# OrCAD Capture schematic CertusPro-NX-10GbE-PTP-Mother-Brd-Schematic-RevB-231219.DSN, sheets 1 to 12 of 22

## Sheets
1 22_PS-FMC_3V3LDO: size A3; title: 22_PS-FMC_3V3_LDO; rev: v2.1
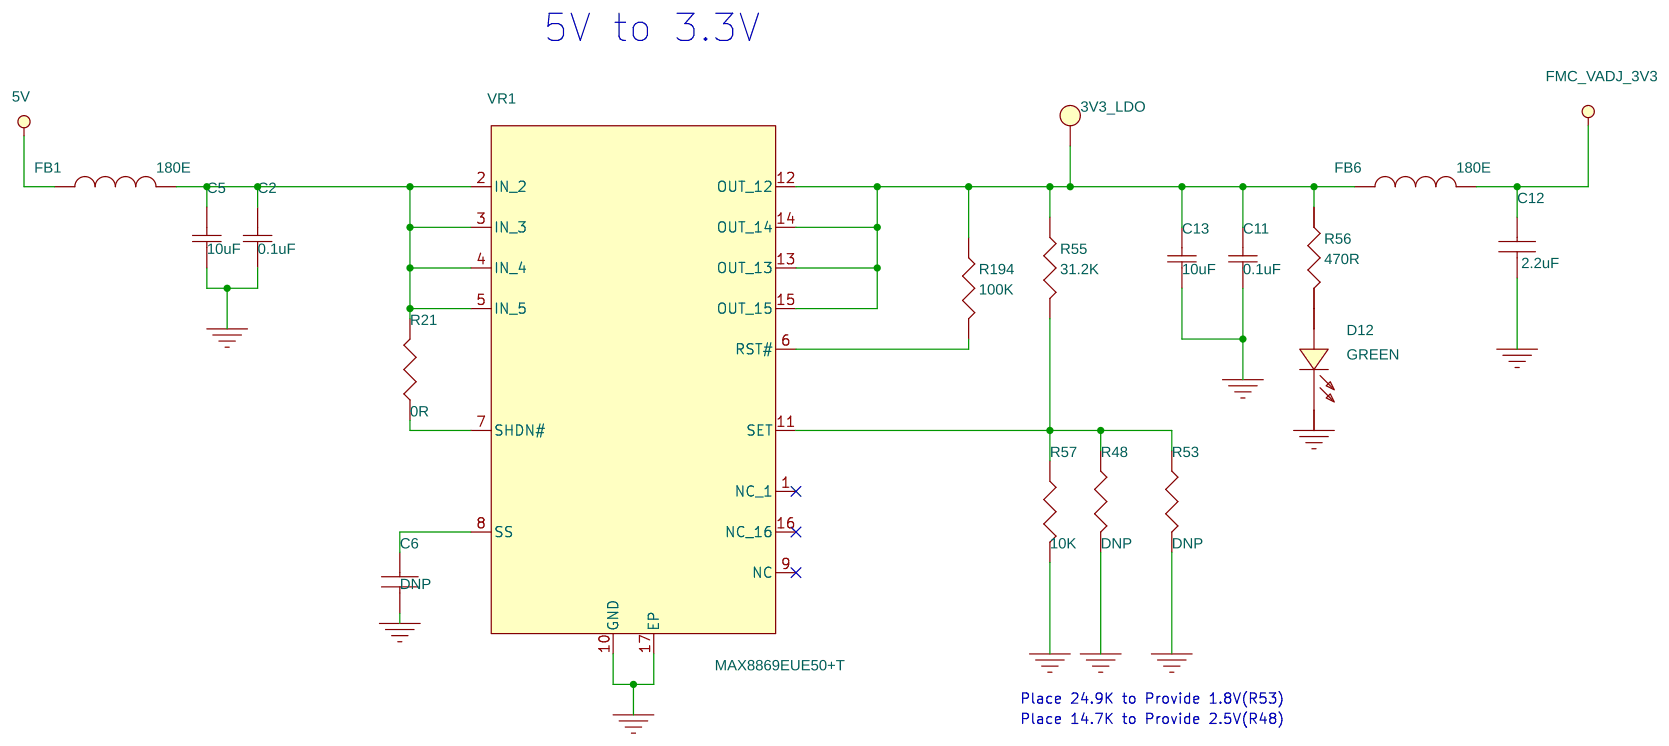
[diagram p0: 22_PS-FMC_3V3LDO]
2 18_FMC_Connector_2: size A3; title: 18_FMC_Connector
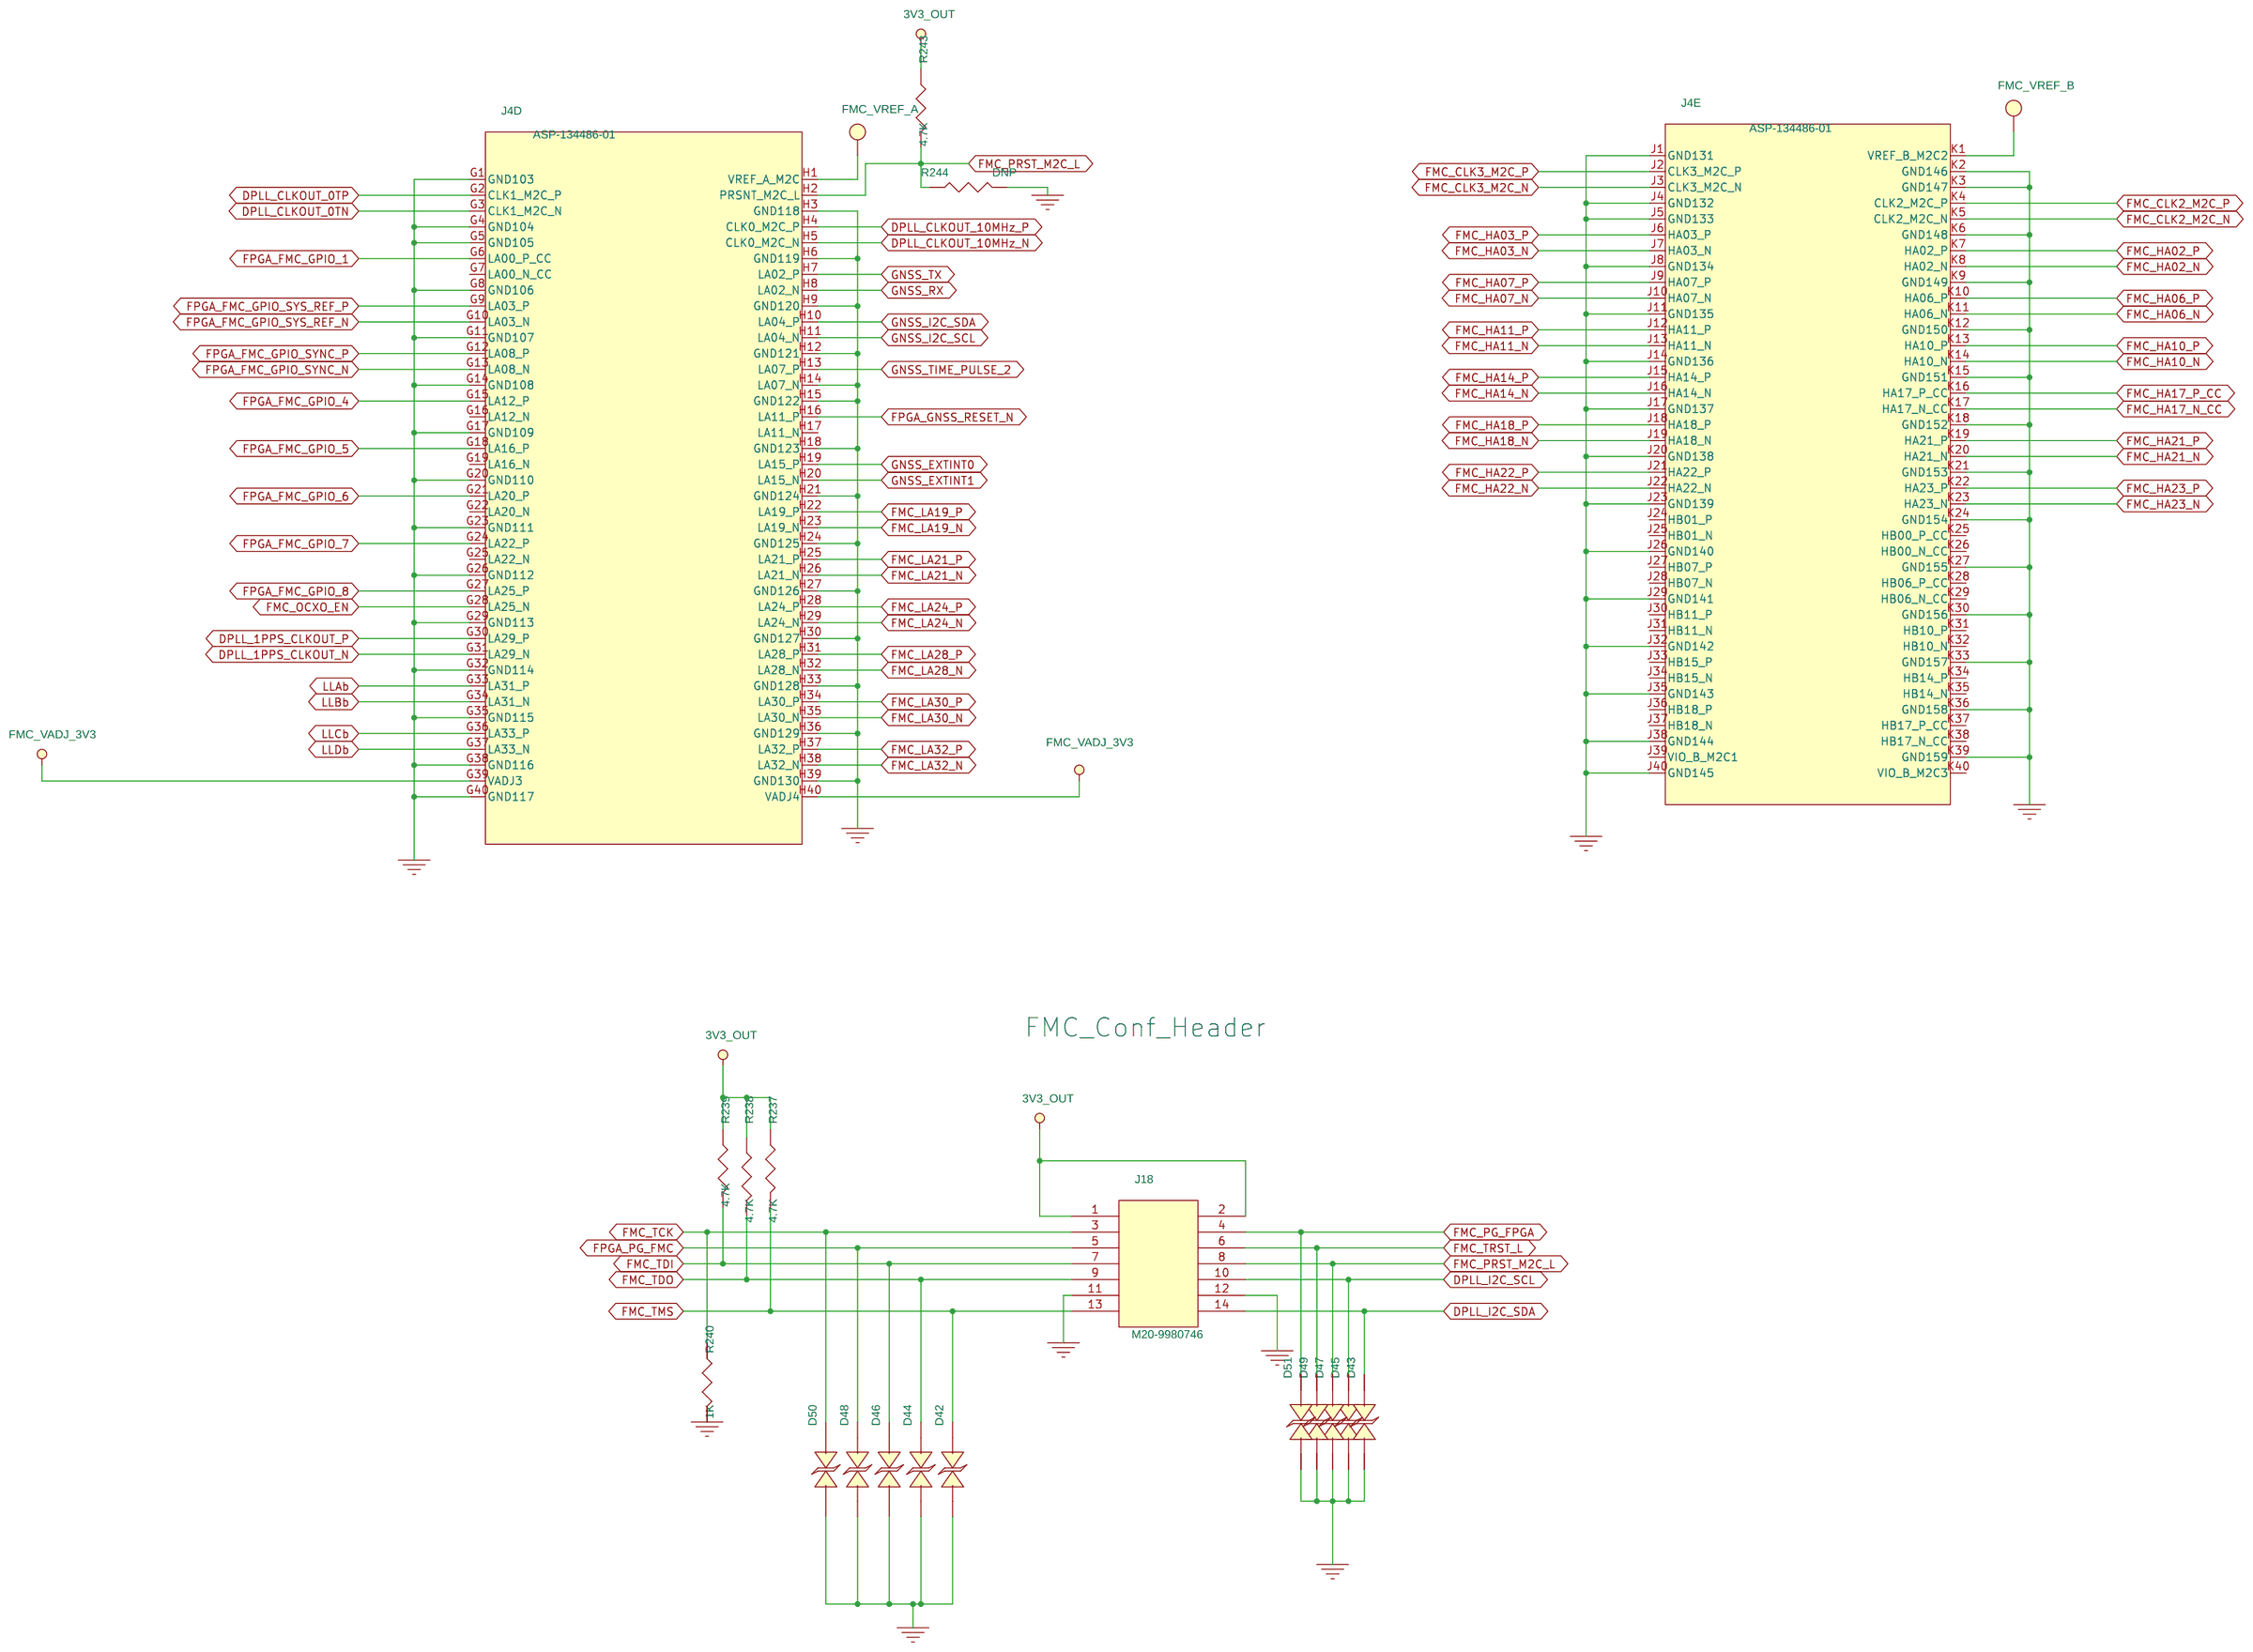
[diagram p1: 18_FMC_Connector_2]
3 04_Clock_Tree: title: 04_Clock_Tree
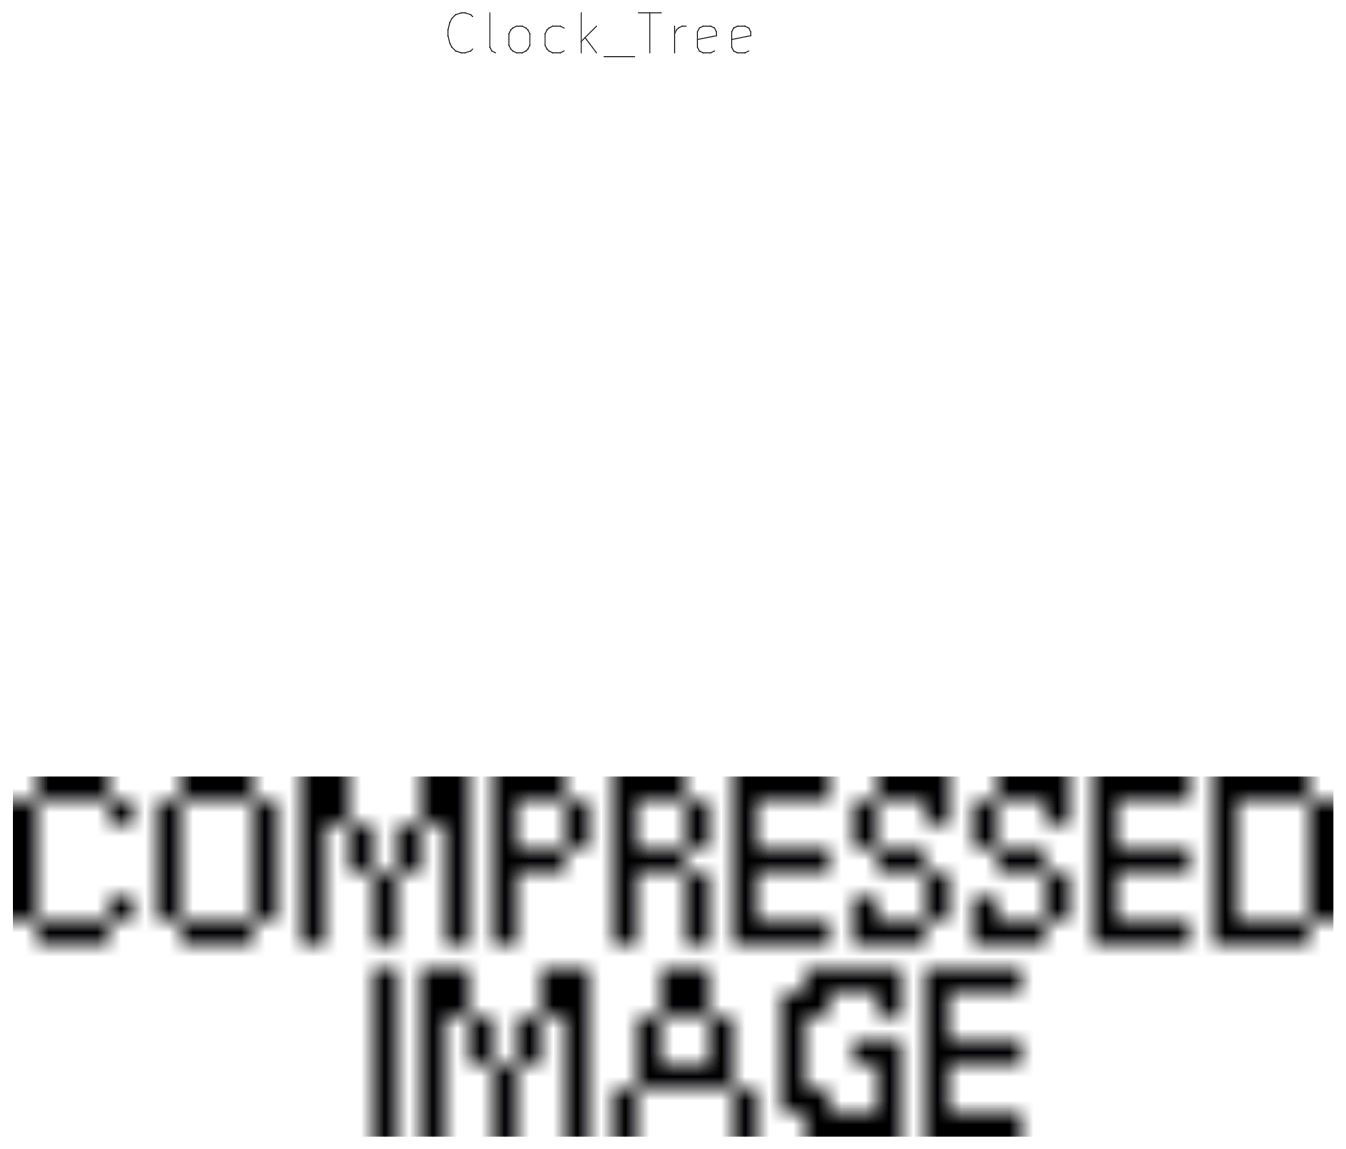
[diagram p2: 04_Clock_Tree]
4 05_PWR_Tree: title: 05_PWR_Tree
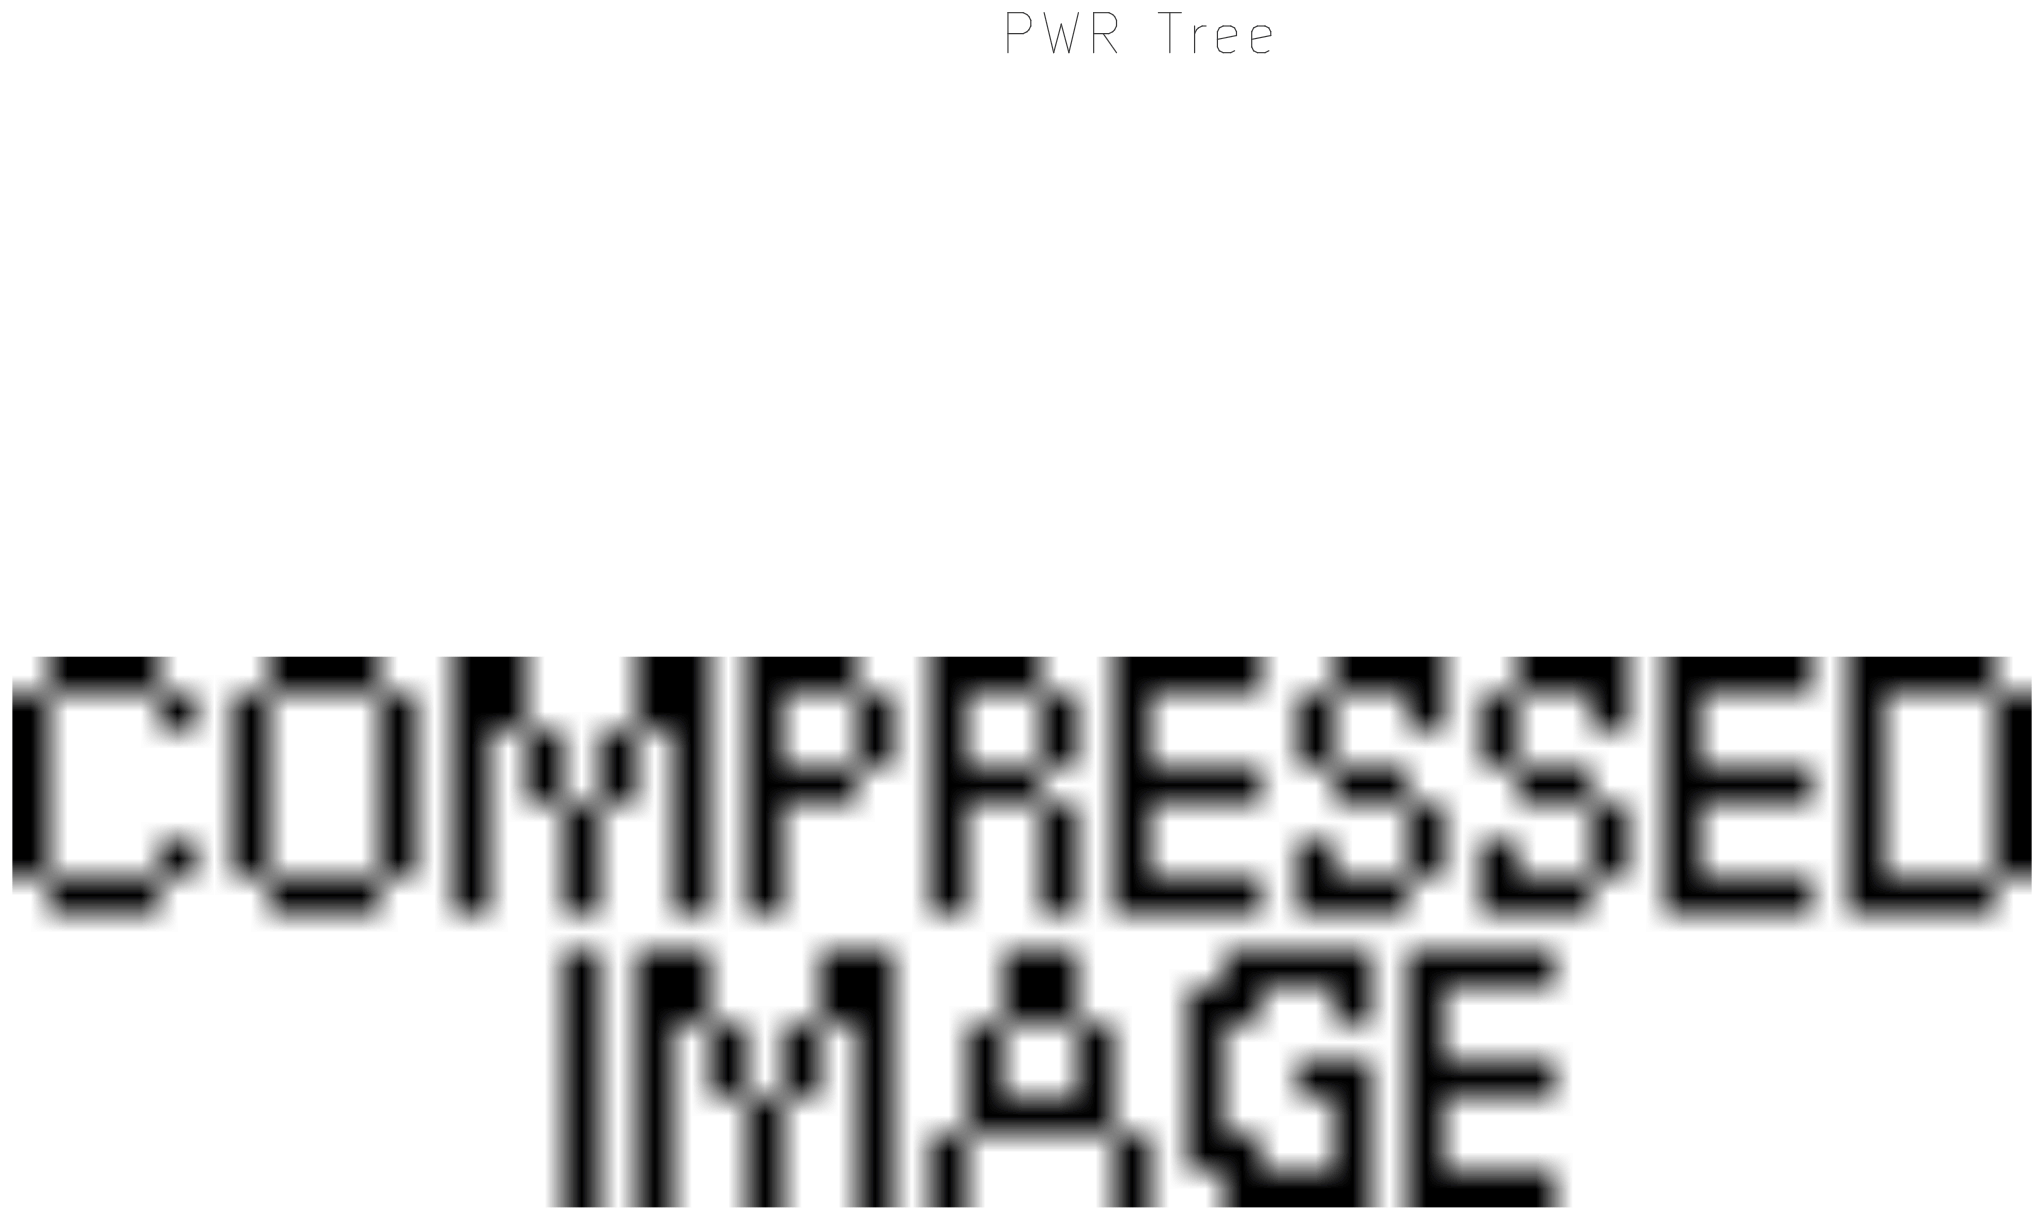
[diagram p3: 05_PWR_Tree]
5 02_Revion_Record: title: 02_Title_Block
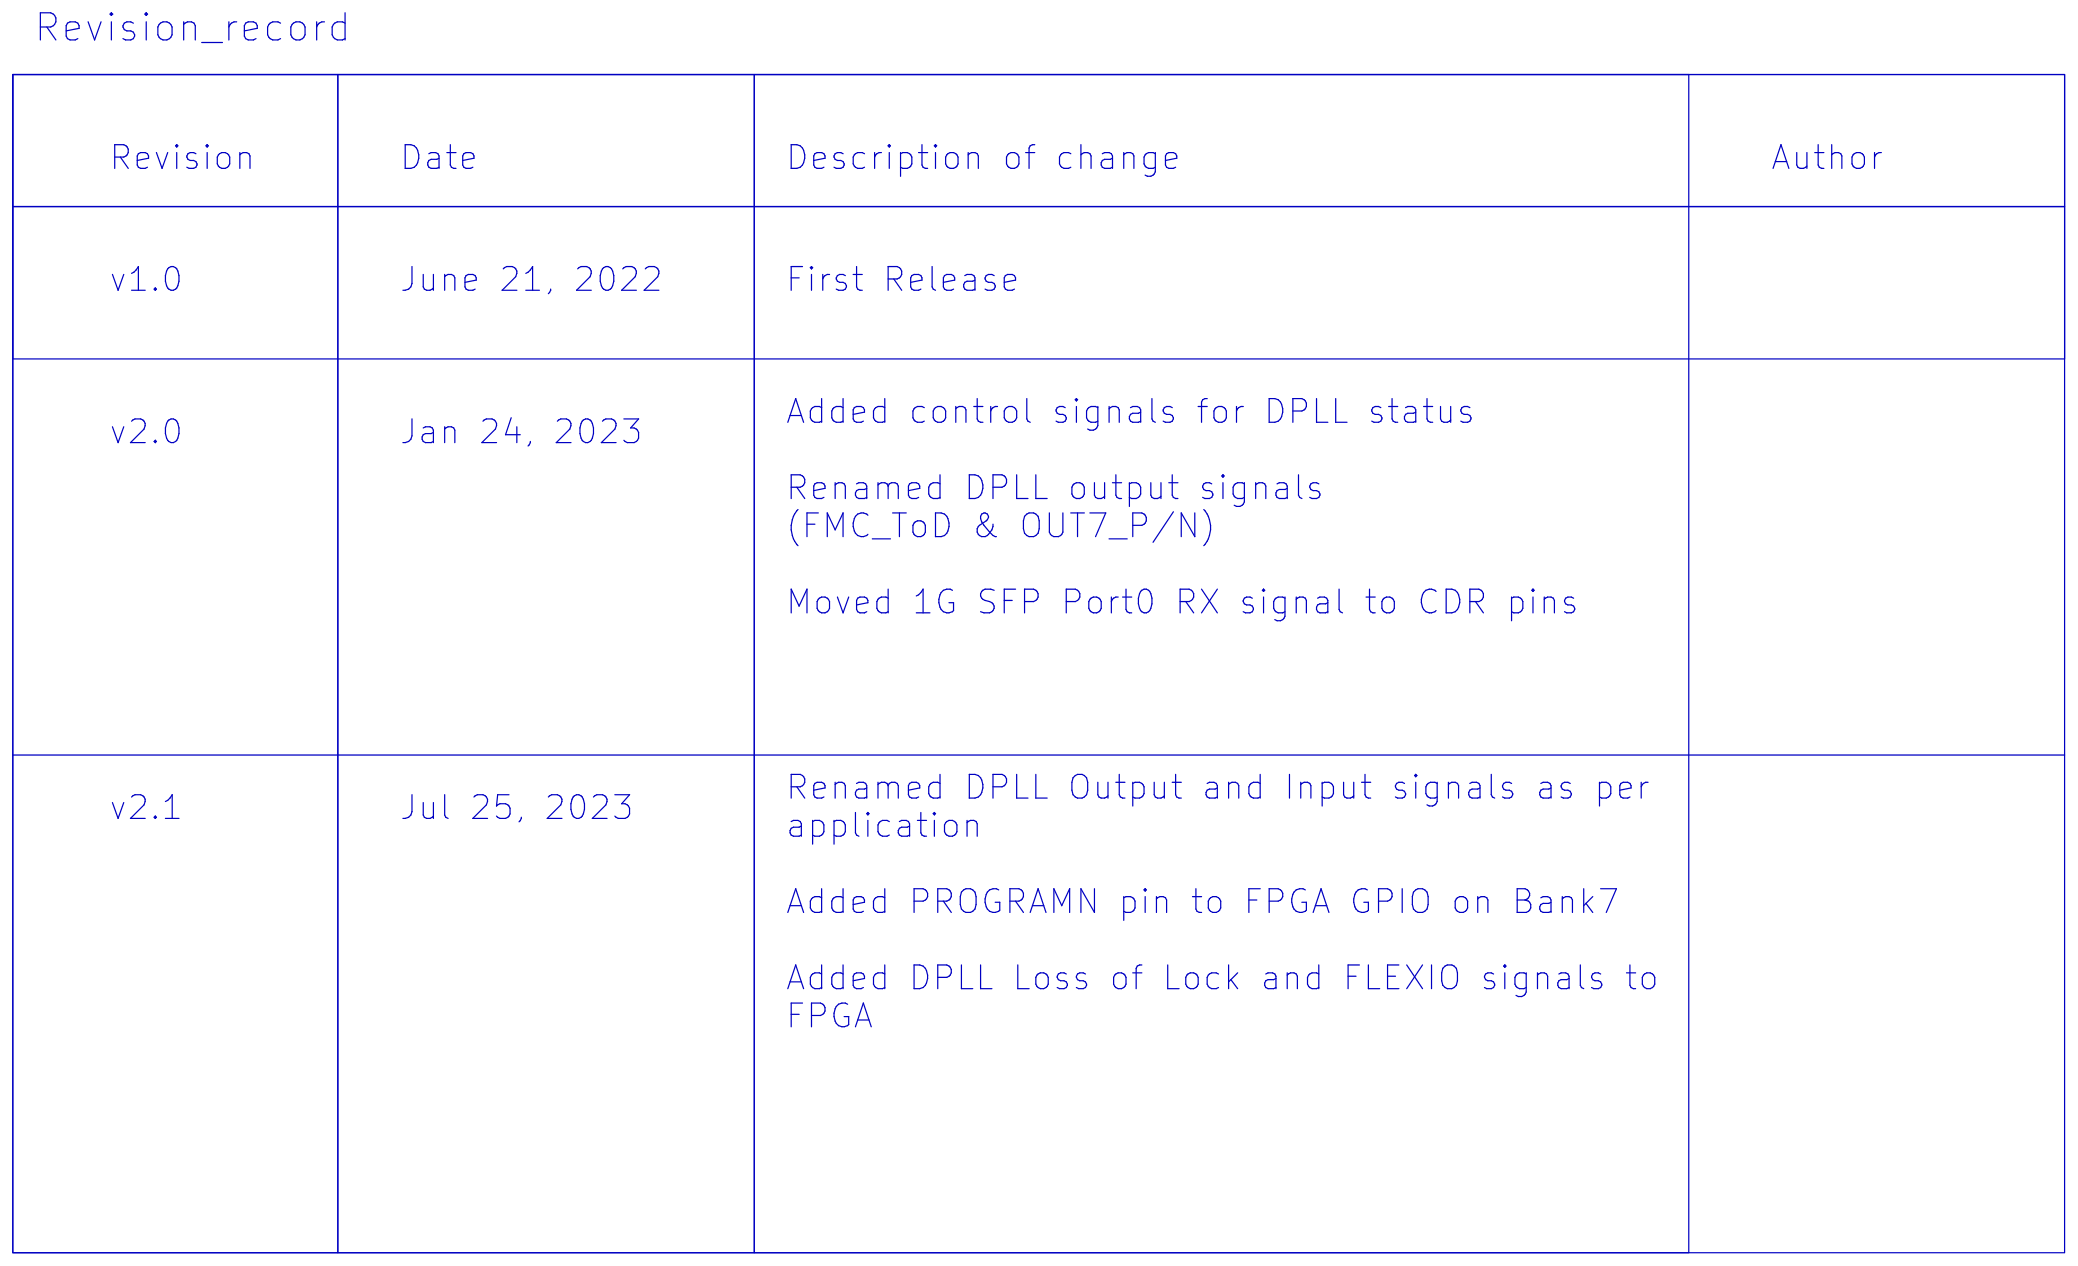
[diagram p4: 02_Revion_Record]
6 13_FPGA_B6-SFPS_Ctrl: size A3; title: 13_FPGA_B6-SFPS_Ctrl
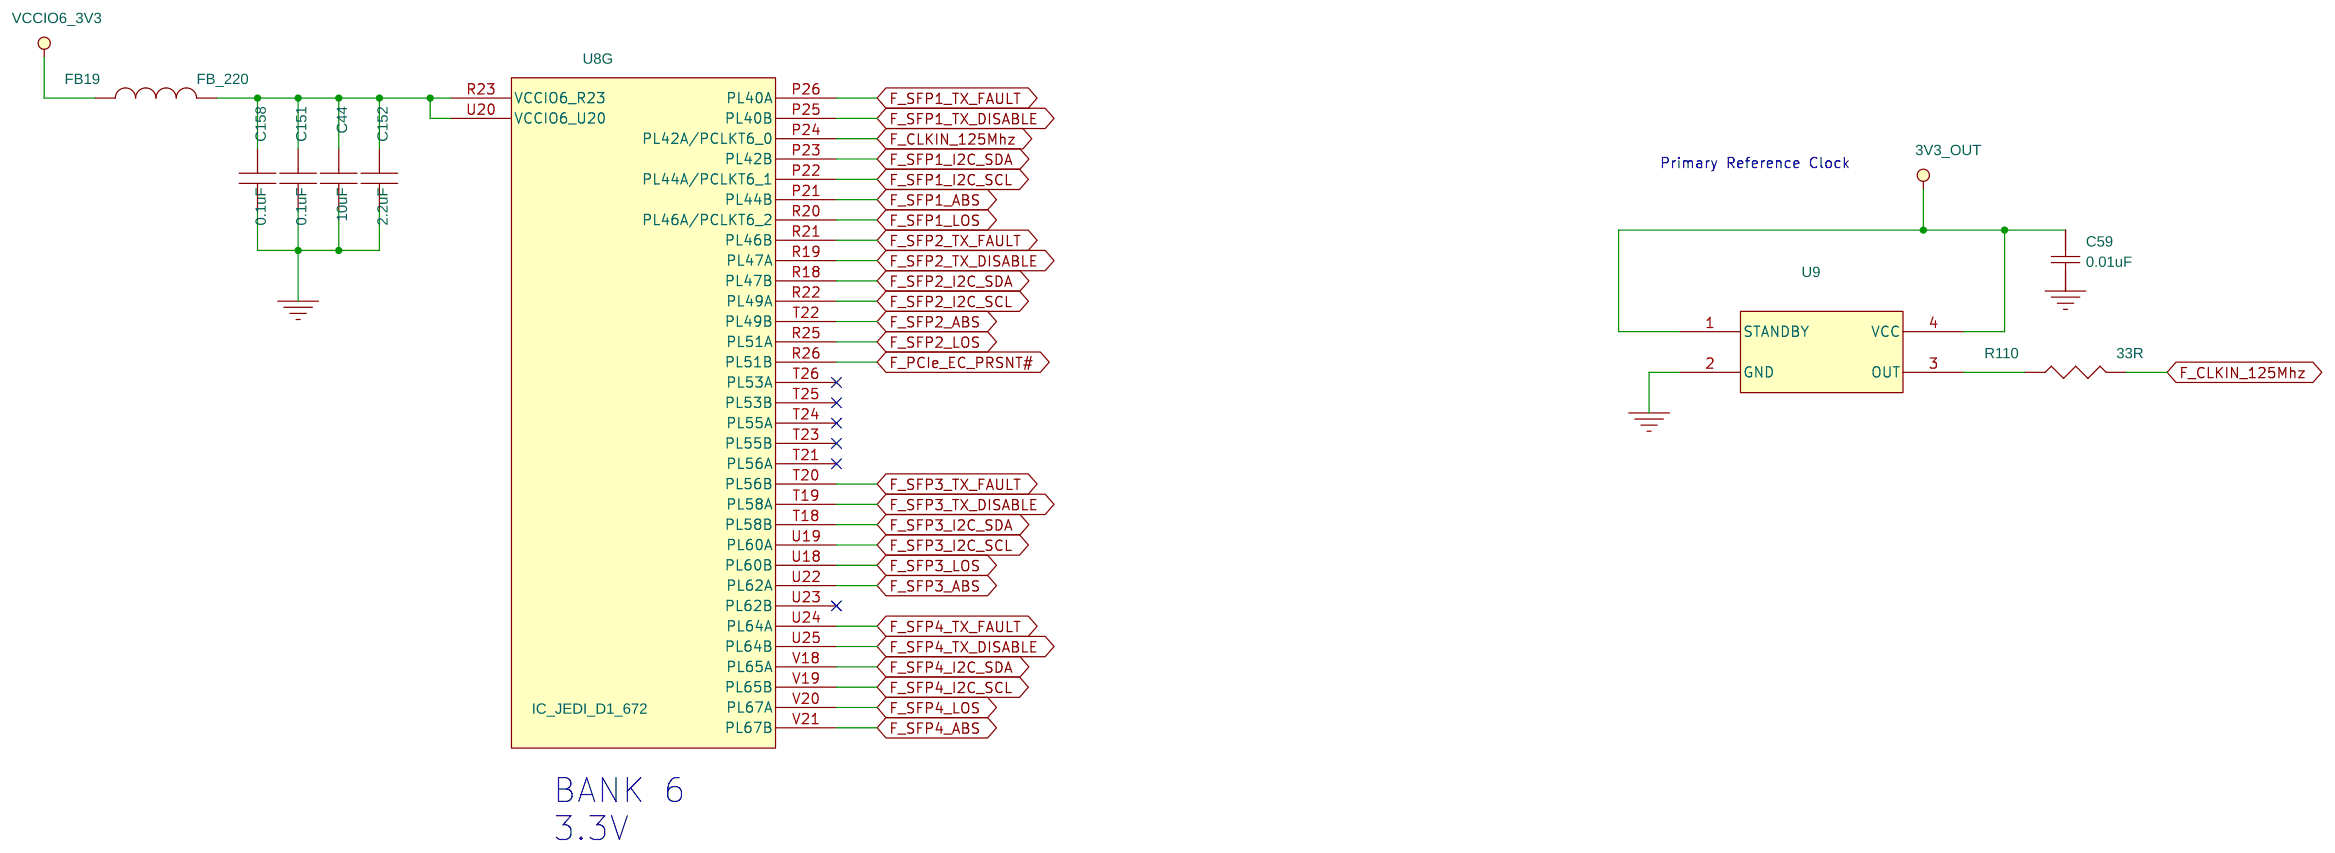
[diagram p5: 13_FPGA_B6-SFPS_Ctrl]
7 17_FMC_Connector_1: size A3; title: 17_FMC_Connector
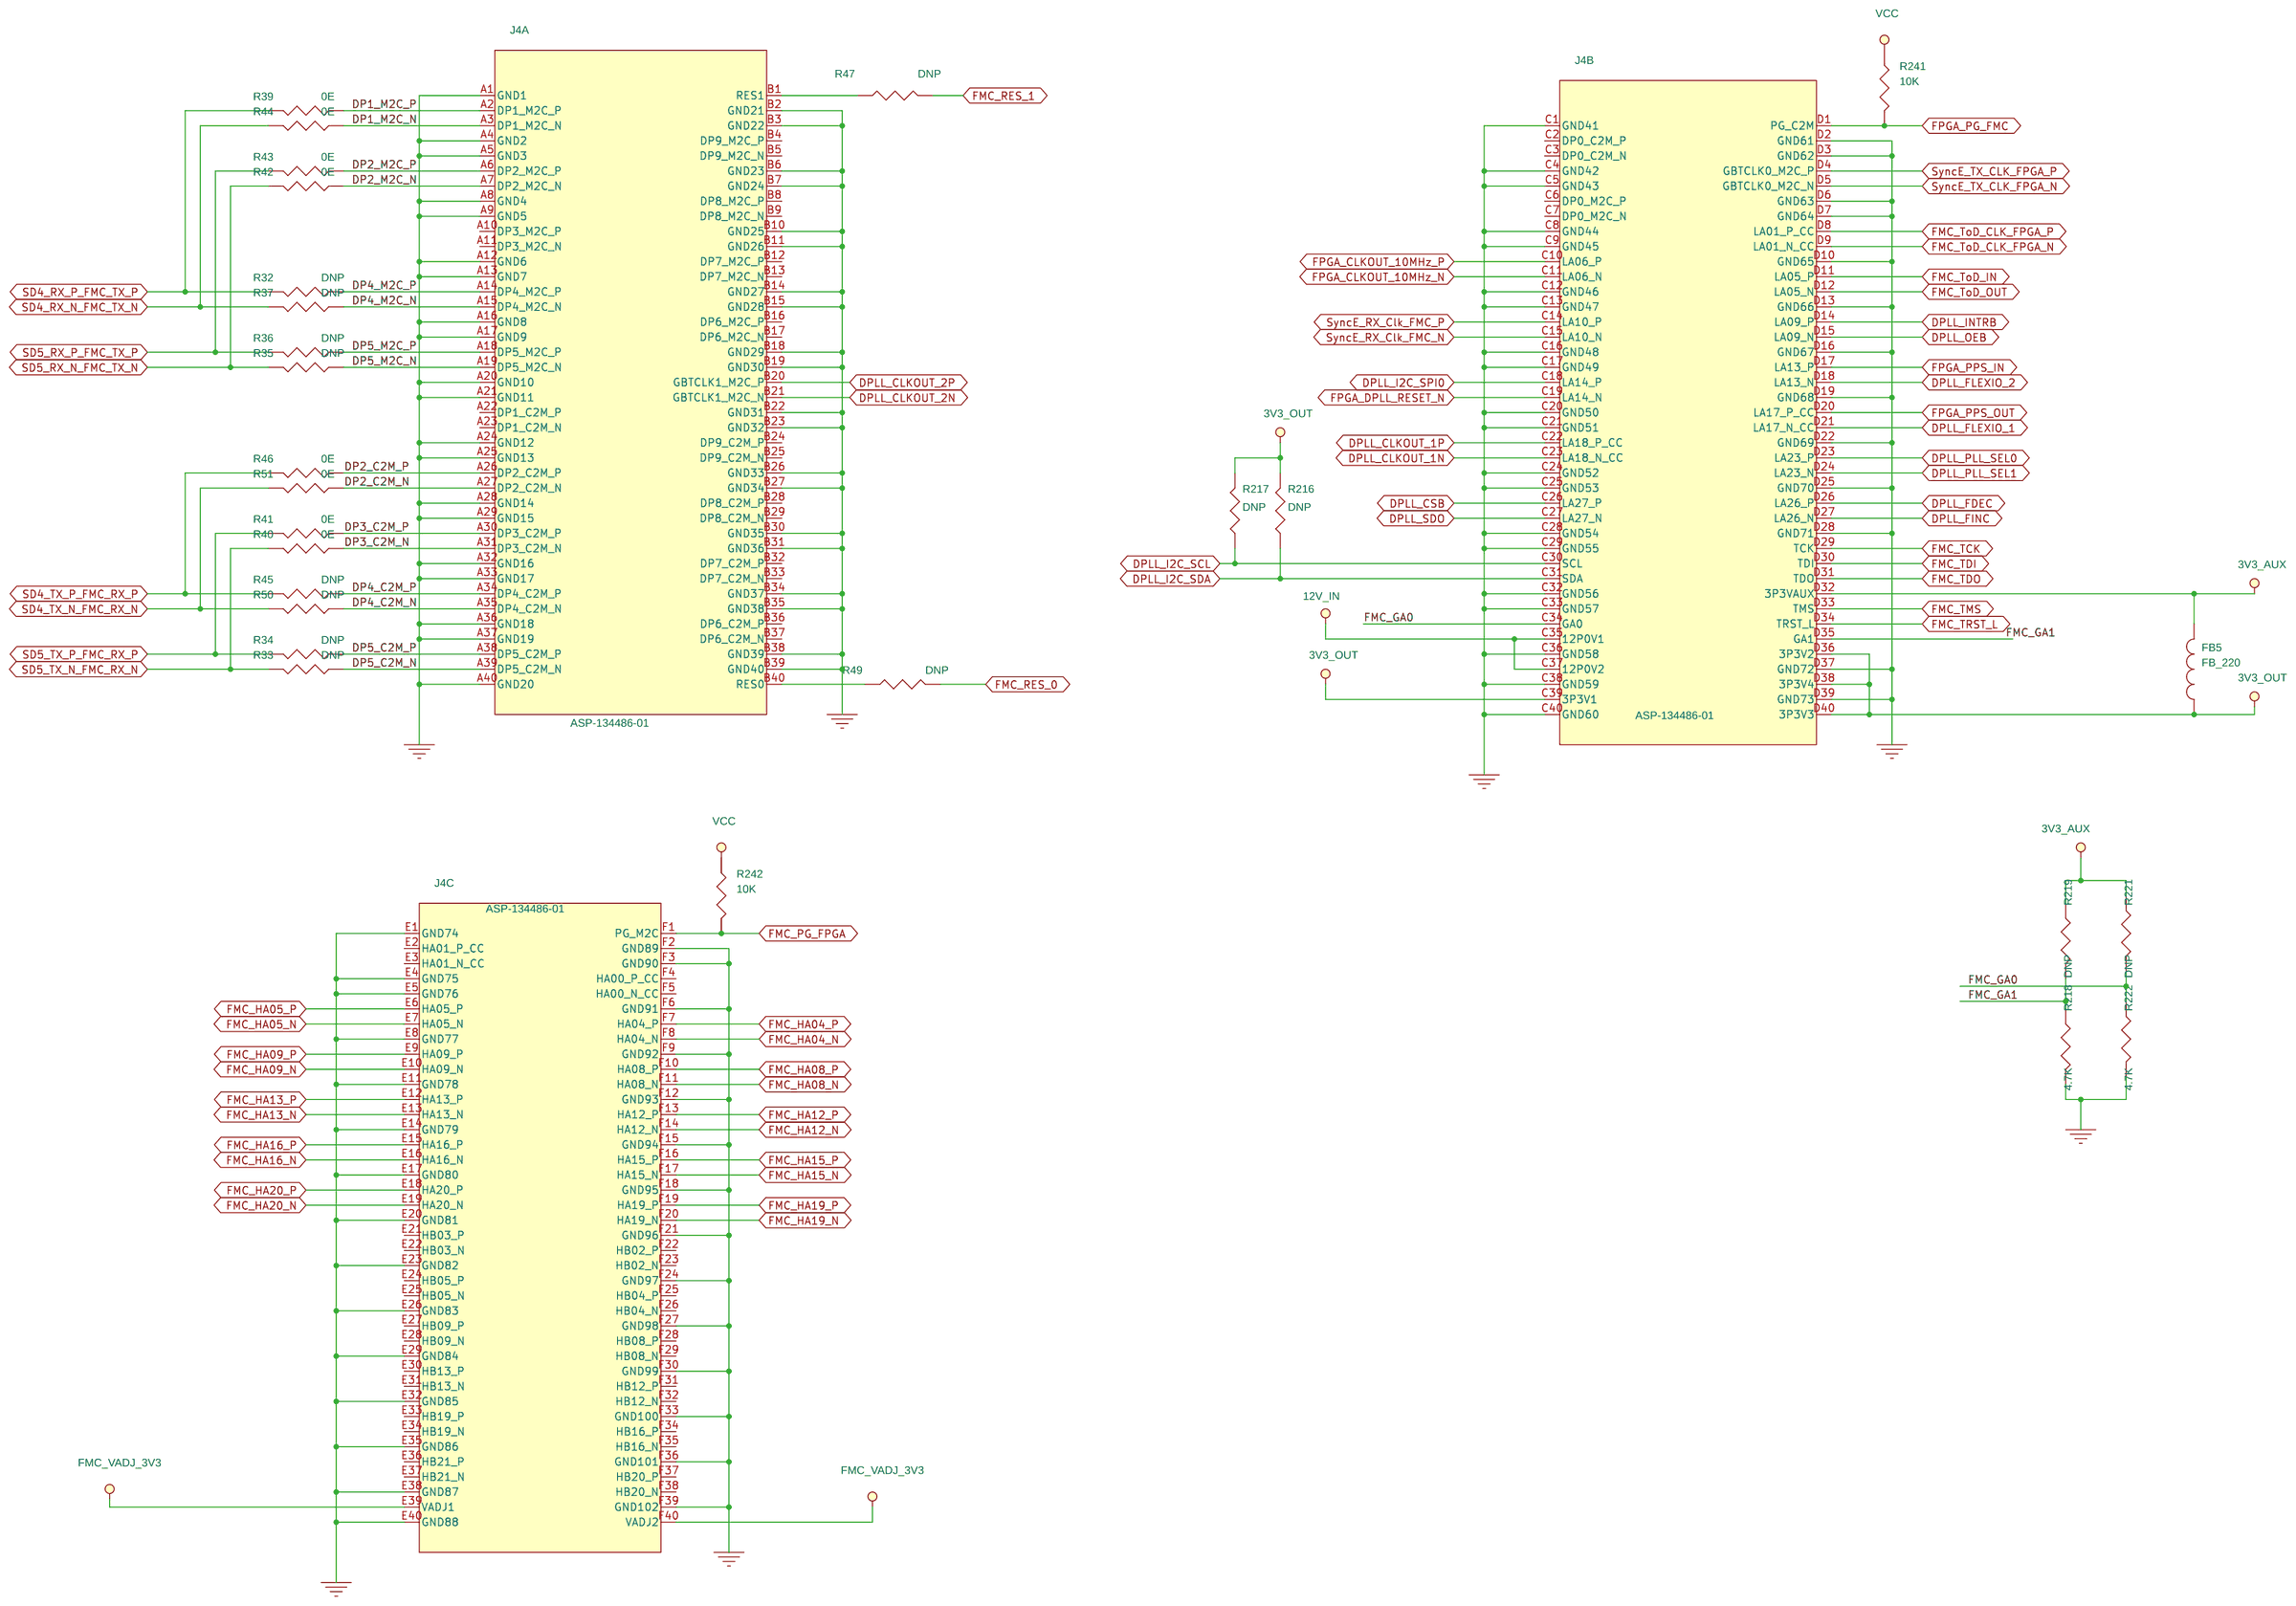
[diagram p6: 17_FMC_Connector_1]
8 21_PS-3V3,1V8LDO,2V5LDO: size A3; title: 21_PS-3V3,1V8LDO,2V5LDO
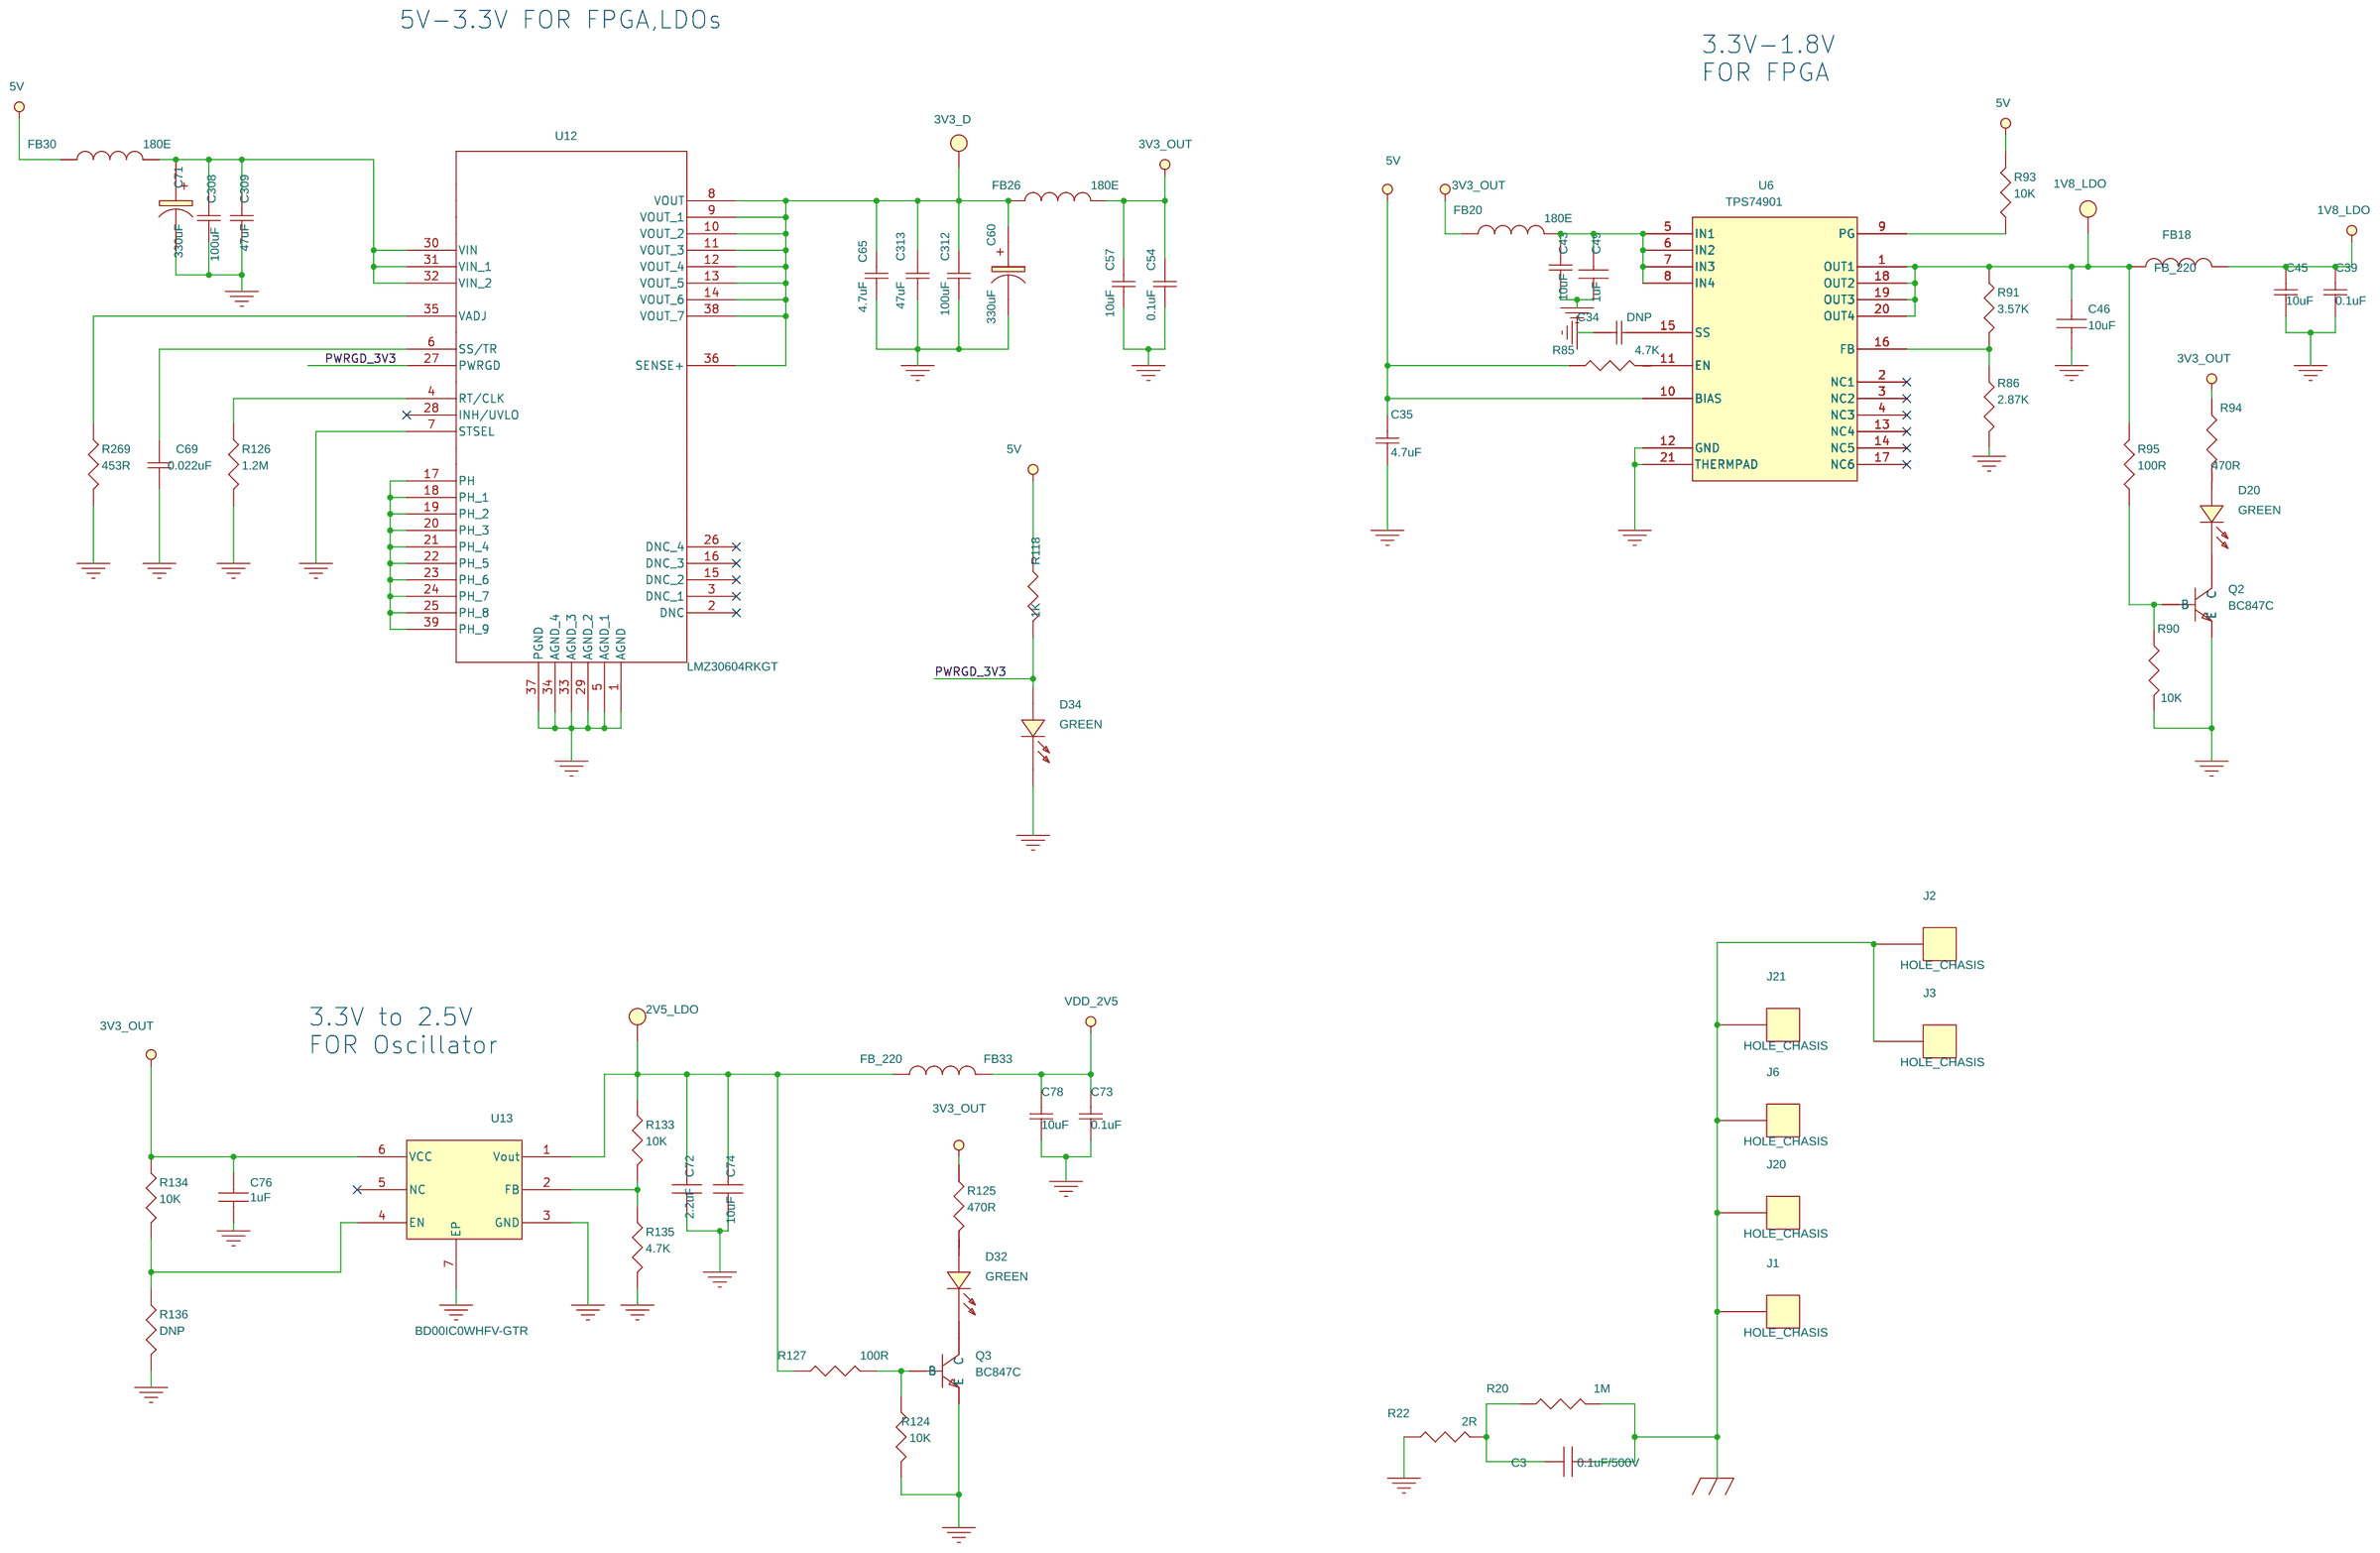
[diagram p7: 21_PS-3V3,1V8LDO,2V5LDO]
9 11_FPGA_B3_B4-FMC: size A3; title: 11_FPGA_B3_B4-FMC
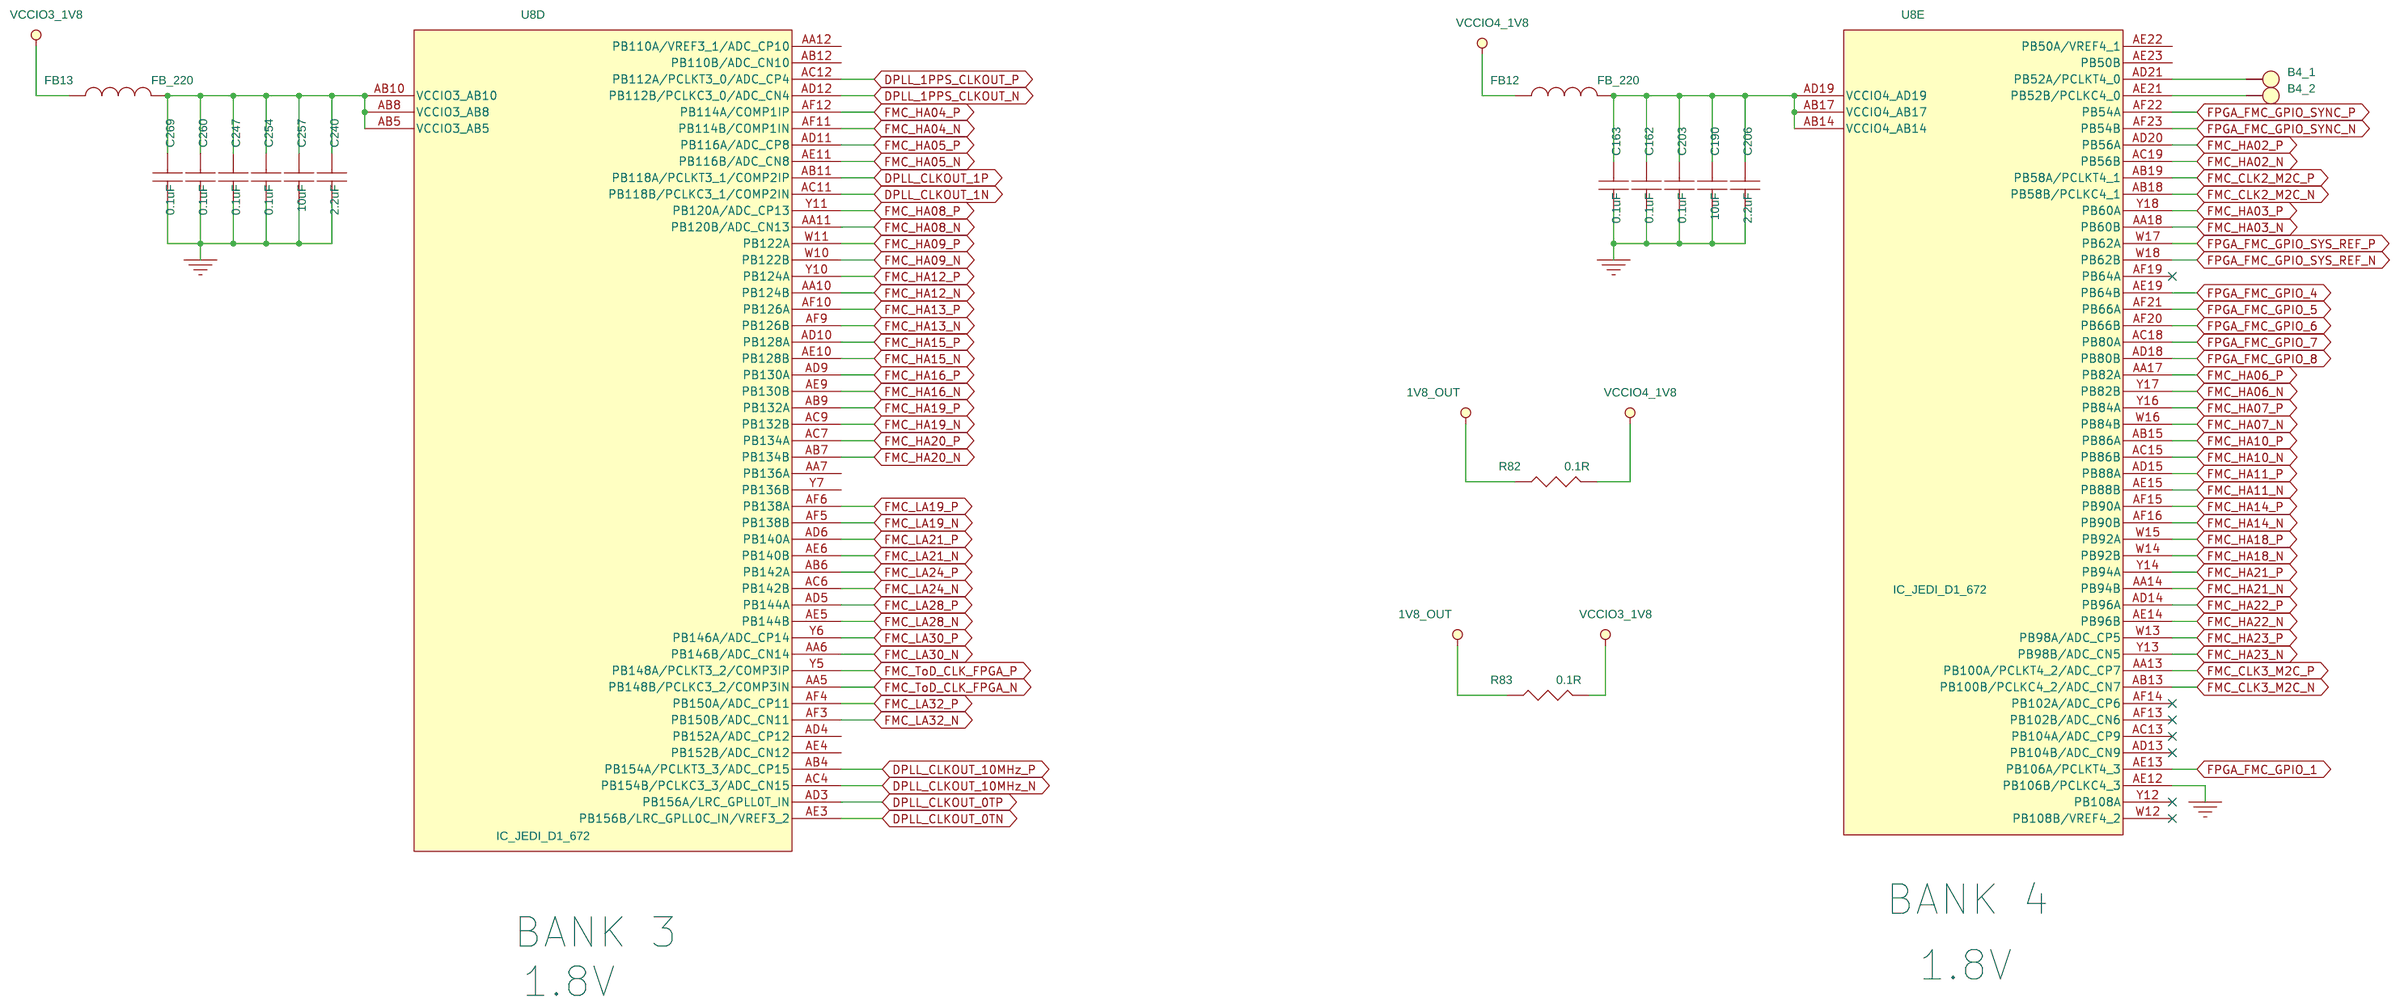
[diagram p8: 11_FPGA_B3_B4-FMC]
10 01_Index: title: 01_Index
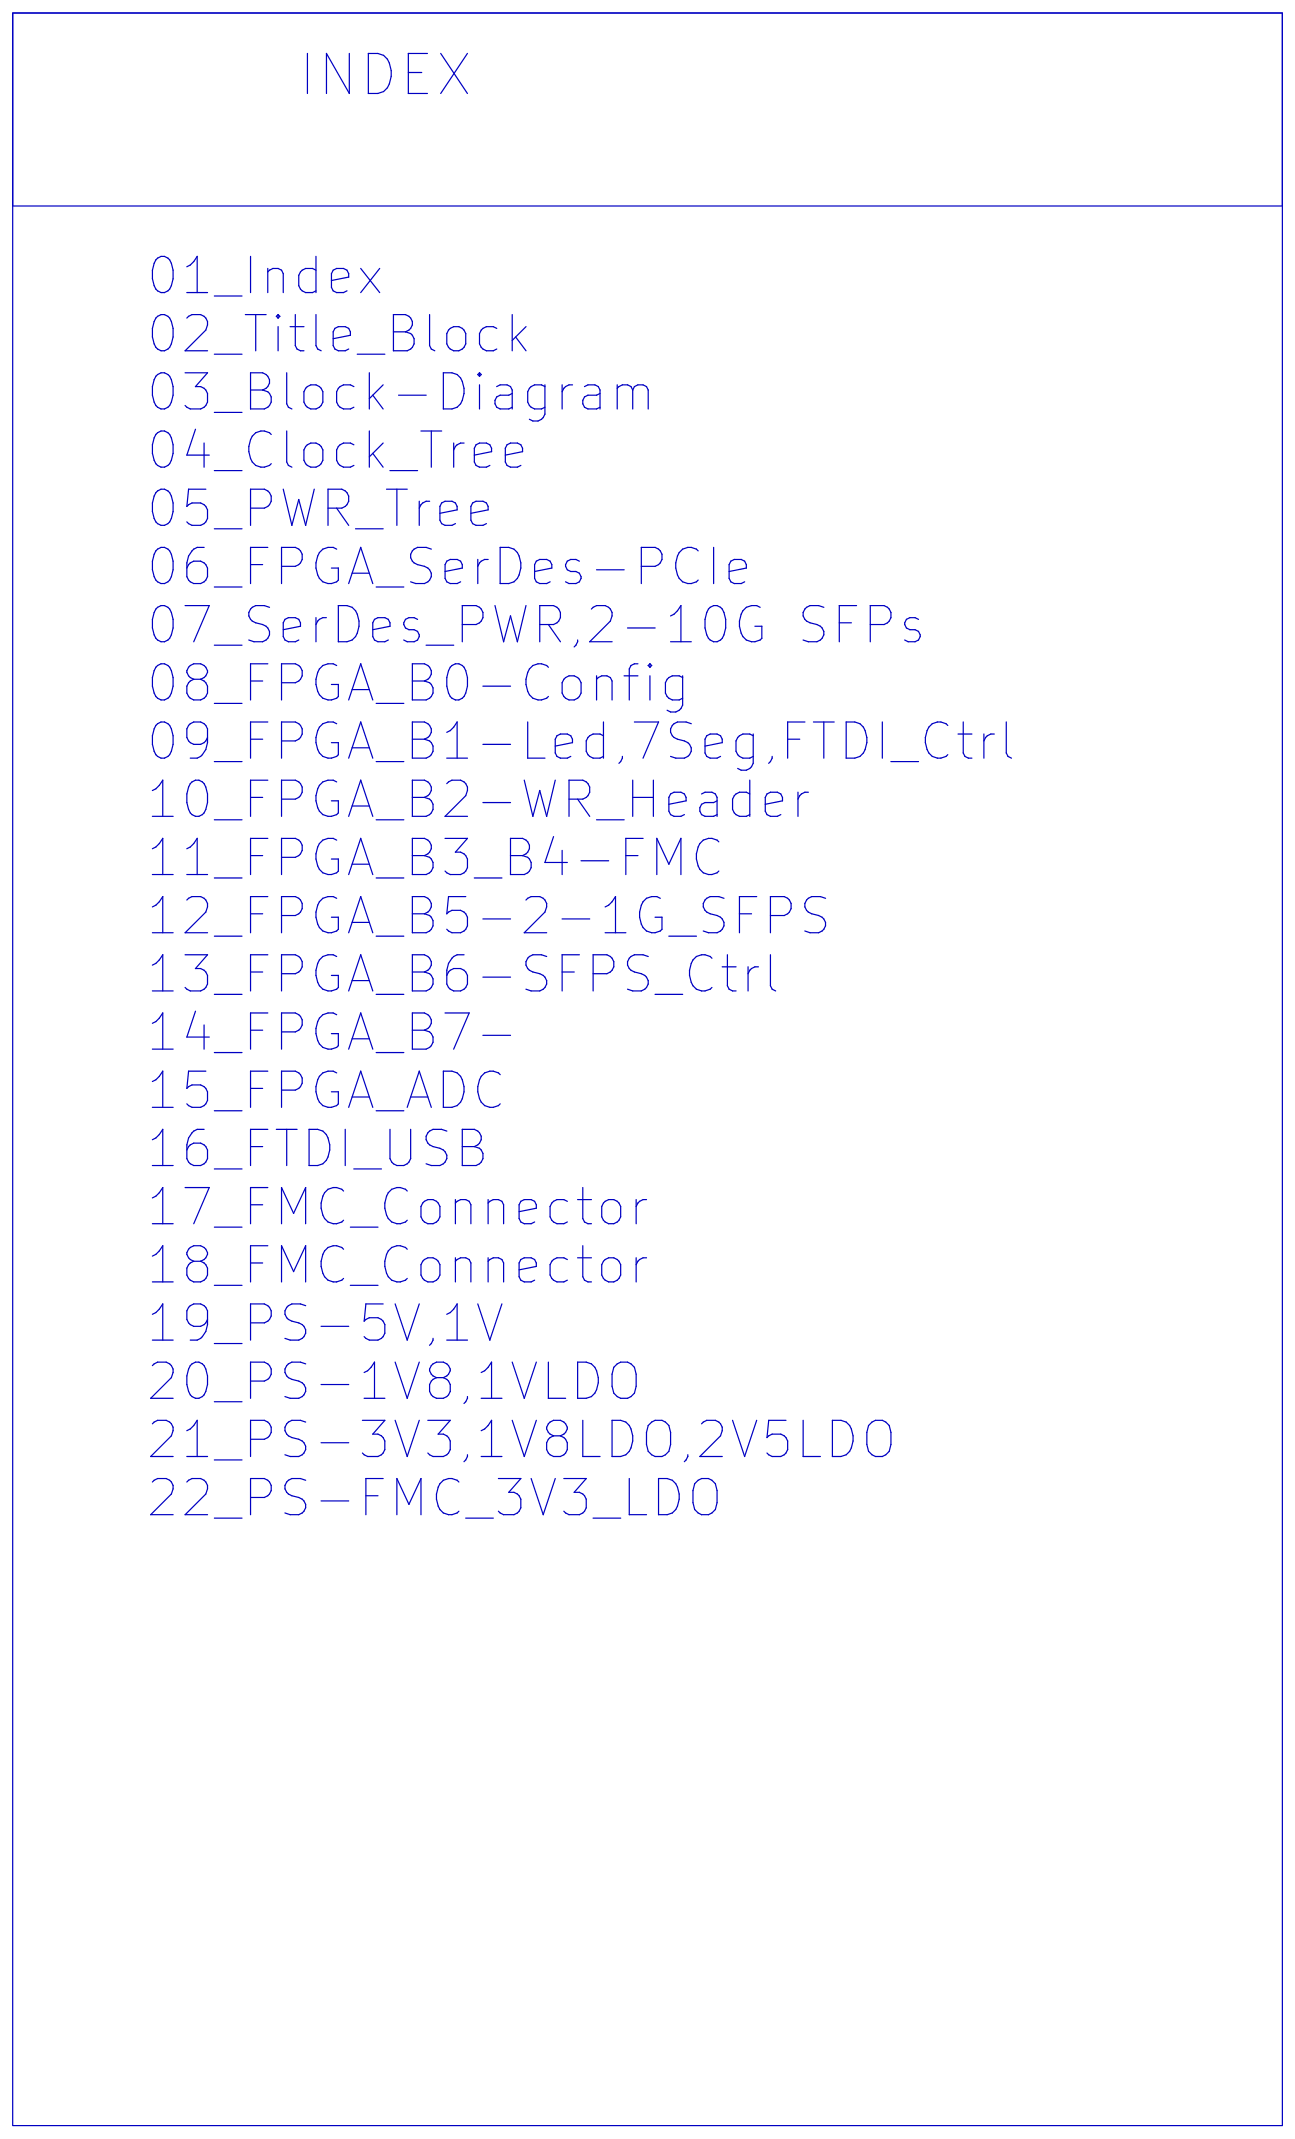
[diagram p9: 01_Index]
11 03_Block_Diagram: title: 03_Block-Diagram
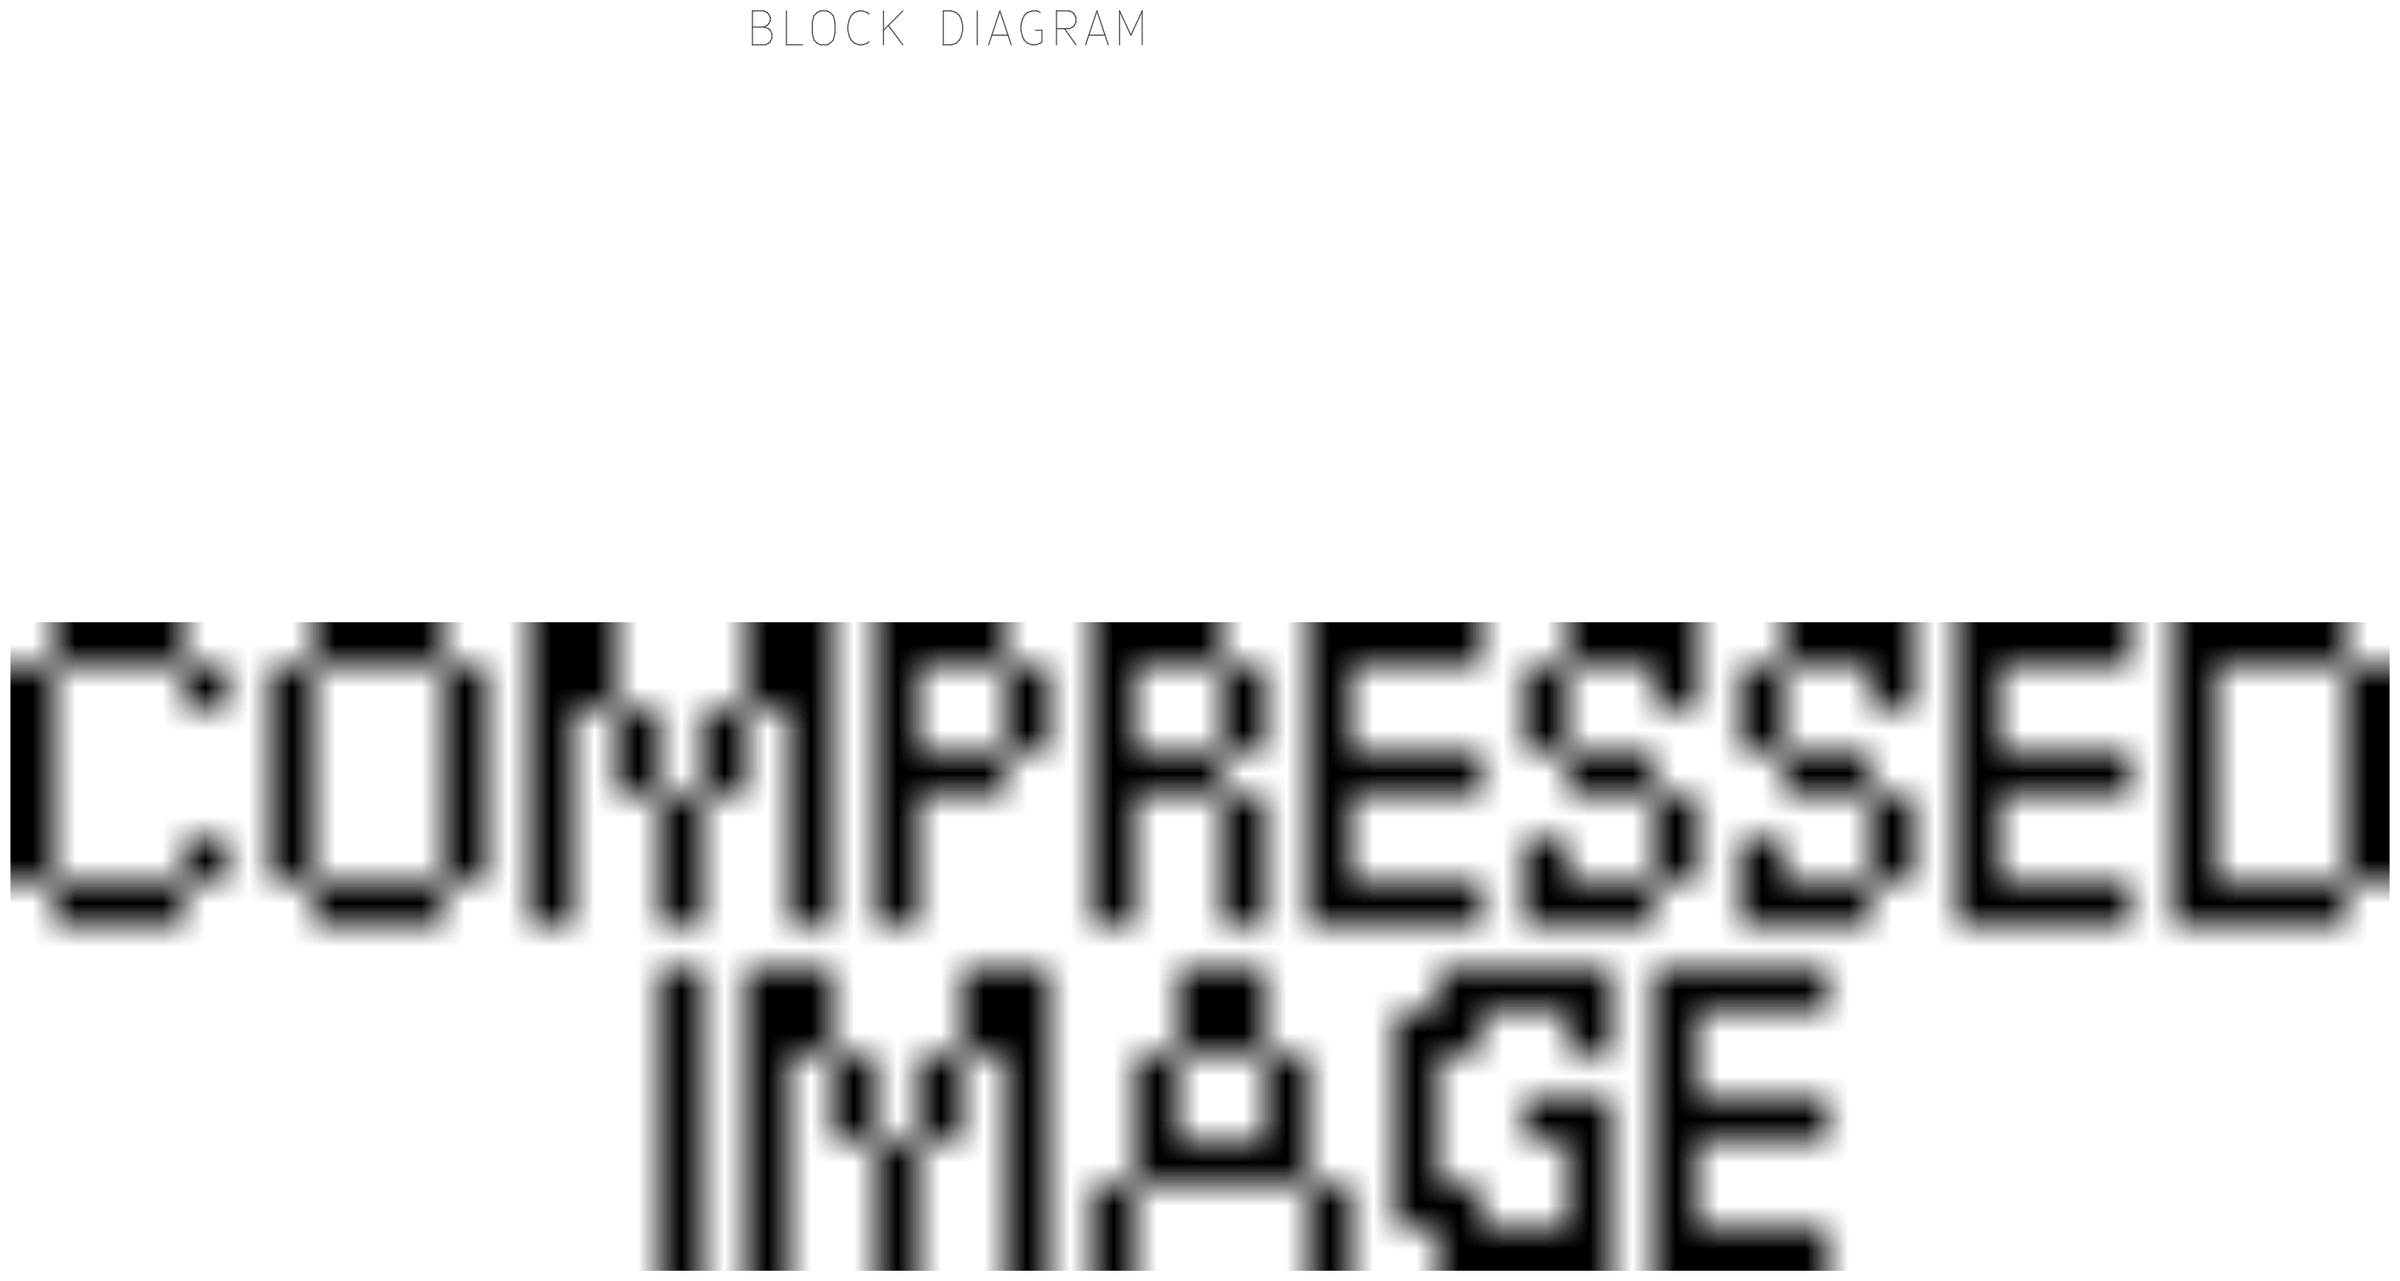
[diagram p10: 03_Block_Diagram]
12 08_FPGA_B0-Config: size A3; title: 08_FPGA_B0-Config
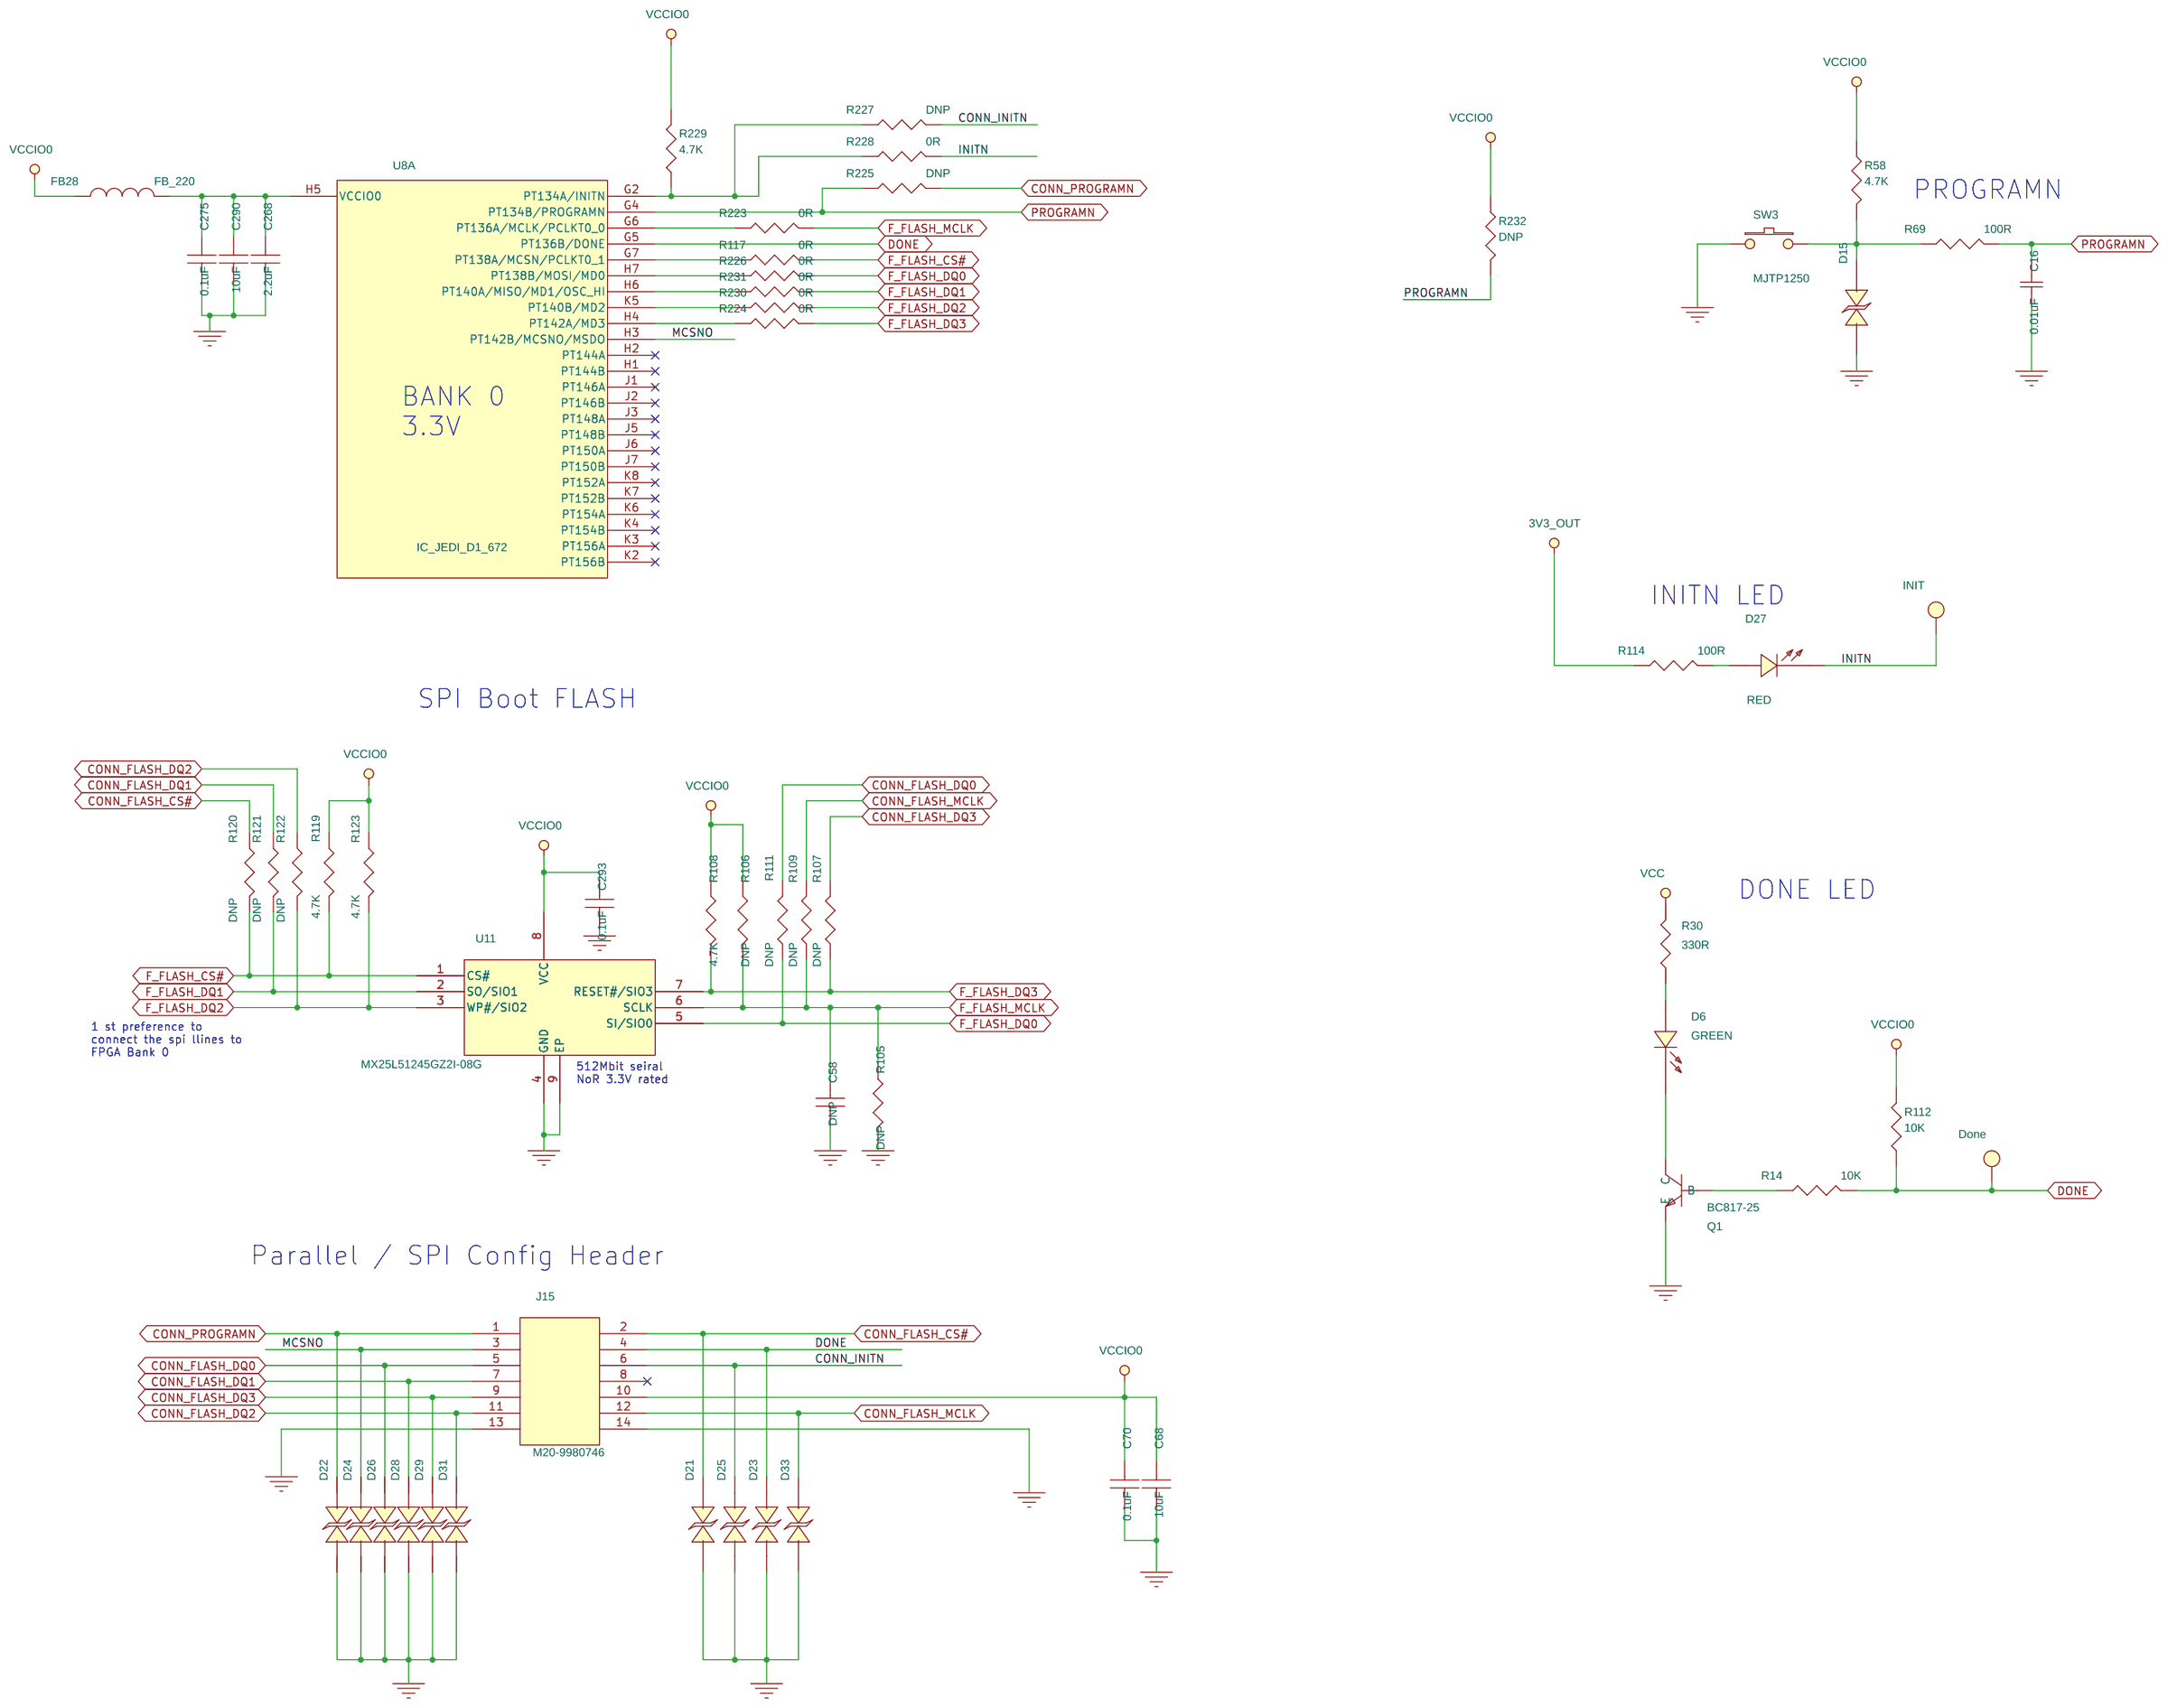
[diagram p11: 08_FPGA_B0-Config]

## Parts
sheet 08_FPGA_B0-Config
C16  0.01uF  [cap0603]
C58  DNP  [cap0603]
C68  10uF  [cap0603]
C70  0.1uF  [cap0402]
C268  2.2uF  [cap0402]
C275  0.1uF  [cap0402]
C290  10uF  [cap0603]
C293  0.1uF  [cap0402]
D6  GREEN  [led_0603]
D15  DIODE_SUPPRESSOR ESD 30VDC 0402  [ESD0402]
D21  DIODE_SUPPRESSOR ESD 30VDC 0402  [ESD0402]
D22  DIODE_SUPPRESSOR ESD 30VDC 0402  [ESD0402]
D23  DIODE_SUPPRESSOR ESD 30VDC 0402  [ESD0402]
D24  DIODE_SUPPRESSOR ESD 30VDC 0402  [ESD0402]
D25  DIODE_SUPPRESSOR ESD 30VDC 0402  [ESD0402]
D26  DIODE_SUPPRESSOR ESD 30VDC 0402  [ESD0402]
D27  RED  [led_0603]
D28  DIODE_SUPPRESSOR ESD 30VDC 0402  [ESD0402]
D29  DIODE_SUPPRESSOR ESD 30VDC 0402  [ESD0402]
D31  DIODE_SUPPRESSOR ESD 30VDC 0402  [ESD0402]
D33  DIODE_SUPPRESSOR ESD 30VDC 0402  [ESD0402]
Done  Done  [TP_50]
FB28  FB_220  [FB0603]
INIT  INIT  [TP_50]
J15  M20-9980746  [14pin_bergstick]
Q1  BC817-25  [SOT23-3]
R14  10K  [res0603]
R30  330R  [res0603]
R58  4.7K  [res0603]
R69  100R  [res0402]
R105  DNP  [res0603]
R106  DNP  [res0603]
R107  DNP  [res0603]
R108  4.7K  [res0603]
R109  DNP  [res0603]
R111  DNP  [res0603]
R112  10K  [res0603]
R114  100R  [res0402]
R117  0R  [res0603]
R119  4.7K  [res0603]
R120  DNP  [res0603]
R121  DNP  [res0603]
R122  DNP  [res0603]
R123  4.7K  [res0603]
R223  0R  [res0603]
R224  0R  [res0603]
R225  DNP  [res0603]
R226  0R  [res0603]
R227  DNP  [res0603]
R228  0R  [res0603]
R229  4.7K  [res0603]
R230  0R  [res0603]
R231  0R  [res0603]
R232  DNP  [res0603]
SW3  MJTP1250  [SW_TH2]
U11  MX25L51245GZ2I-08G  [8-WSON]
sheet 11_FPGA_B3_B4-FMC
B4_1  1V8P  [TP_50]
B4_2  1V8P  [TP_50]
C162  0.1uF  [cap0402]
C163  0.1uF  [cap0402]
C190  10uF  [cap0603]
C203  0.1uF  [cap0402]
C206  2.2uF  [cap0402]
C240  2.2uF  [cap0402]
C247  0.1uF  [cap0402]
C254  0.1uF  [cap0402]
C257  10uF  [cap0603]
C260  0.1uF  [cap0402]
C269  0.1uF  [cap0402]
FB12  FB_220  [FB0603]
FB13  FB_220  [FB0603]
R82  0.1R  [res0603]
R83  0.1R  [res0603]
sheet 13_FPGA_B6-SFPS_Ctrl
C44  10uF  [cap0603]
C59  0.01uF  [cap0603]
C151  0.1uF  [cap0402]
C152  2.2uF  [cap0402]
C158  0.1uF  [cap0402]
FB19  FB_220  [FB0603]
R110  33R  [res0402]
U9  125MHz  [osc_32x25_4pin_25mhz]
sheet 17_FMC_Connector_1
FB5  FB_220  [FB0603]
R32  DNP  [res0201]
R33  DNP  [res0201]
R34  DNP  [res0201]
R35  DNP  [res0201]
R36  DNP  [res0201]
R37  DNP  [res0201]
R39  0E  [res0201]
R40  0E  [res0201]
R41  0E  [res0201]
R42  0E  [res0201]
R43  0E  [res0201]
R44  0E  [res0201]
R45  DNP  [res0201]
R46  0E  [res0201]
R47  DNP  [res0402]
R49  DNP  [res0402]
R50  DNP  [res0201]
R51  0E  [res0201]
R216  DNP  [res0402]
R217  DNP  [res0402]
R218  4.7K  [res0402]
R219  DNP  [res0402]
R221  DNP  [res0402]
R222  4.7K  [res0402]
R241  10K  [res0402]
R242  10K  [res0402]
sheet 18_FMC_Connector_2
D42  DIODE_SUPPRESSOR ESD 30VDC 0402  [ESD0402]
D43  DIODE_SUPPRESSOR ESD 30VDC 0402  [ESD0402]
D44  DIODE_SUPPRESSOR ESD 30VDC 0402  [ESD0402]
D45  DIODE_SUPPRESSOR ESD 30VDC 0402  [ESD0402]
D46  DIODE_SUPPRESSOR ESD 30VDC 0402  [ESD0402]
D47  DIODE_SUPPRESSOR ESD 30VDC 0402  [ESD0402]
D48  DIODE_SUPPRESSOR ESD 30VDC 0402  [ESD0402]
D49  DIODE_SUPPRESSOR ESD 30VDC 0402  [ESD0402]
D50  DIODE_SUPPRESSOR ESD 30VDC 0402  [ESD0402]
D51  DIODE_SUPPRESSOR ESD 30VDC 0402  [ESD0402]
FMC_VREF_A  FMC_VREF_A  [TP_50]
FMC_VREF_B  FMC_VREF_B  [TP_50]
J4  ASP-134486-01  [ASP-134486-01]  (sections A,B,C,D,E)
J18  M20-9980746  [14pin_bergstick]
R237  4.7K  [res0402]
R238  4.7K  [res0402]
R239  4.7K  [res0402]
R240  1K  [res0402]
R243  4.7K  [res0402]
R244  DNP  [res0402]
sheet 19_PS-5V,1V
U8  IC_JEDI_D1_672  [FPGA-672]  (sections A,B,C,D,E,F,G,H,I,J,K,L,M,N,O)
sheet 21_PS-3V3,1V8LDO,2V5LDO
1V8_LDO  1V8_LDO  [TP_50]
2V5_LDO  2V5_LDO  [TP_50]
3V3_D  3V3_D  [TP_50]
C3  0.1uF/500V  [cap1210]
C34  DNP  [cap0603]
C35  4.7uF  [cap0402]
C39  0.1uF  [cap0402]
C43  10uF  [cap0603]
C45  10uF  [cap0603]
C46  10uF  [cap0603]
C49  1uF  [cap0603]
C54  0.1uF  [cap0402]
C57  10uF  [cap0603]
C60  330uF  [cap2917]
C65  4.7uF  [cap0603]
C69  0.022uF  [cap0603]
C71  330uF  [cap2917]
C72  2.2uF  [CAP0402]
C73  0.1uF  [cap0402]
C74  10uF  [cap0603]
C76  1uF  [cap0603]
C78  10uF  [cap0603]
C308  100uF  [cap1206]
C309  47uF  [cap1206]
C312  100uF  [cap1206]
C313  47uF  [cap1206]
D20  GREEN  [led_0603]
D32  GREEN  [led_0603]
D34  GREEN  [led_0603]
FB18  FB_220  [FB0603]
FB20  180E  [FB0805]
FB26  180E  [FB0805]
FB30  180E  [FB0805]
FB33  FB_220  [FB0603]
J1  HOLE_CHASIS  [hole35mmheader]
J2  HOLE_CHASIS  [hole35mmheader]
J3  HOLE_CHASIS  [hole35mmheader]
J6  HOLE_CHASIS  [hole35mmheader]
J20  HOLE_CHASIS  [hole35mmheader]
J21  HOLE_CHASIS  [hole35mmheader]
Q2  BC847C  [sot23_3]
Q3  BC847C  [sot23_3]
R20  1M  [res0805]
R22  2R  [res0805]
R85  4.7K  [res0603]
R86  2.87K  [res0402]
R90  10K  [res0402]
R91  3.57K  [res0402]
R93  10K  [res0603]
R94  470R  [res0402]
R95  100R  [res0402]
R118  1K  [res0603]
R124  10K  [res0402]
R125  470R  [res0402]
R126  1.2M  [res0603]
R127  100R  [res0402]
R133  10K  [res0603]
R134  10K  [res0603]
R135  4.7K  [res0603]
R136  DNP  [res0603]
R269  453R  [res0603]
U6  TPS74901  [vqfn_20]
U12  LMZ30604RKGT  [RKG39]
U13  BD00IC0WHFV-GTR  [6-HVSOF]
sheet 22_PS-FMC_3V3LDO
3V3_LDO  3V3_LDO  [TP_50]
C2  0.1uF  [cap0402]
C5  10uF  [cap0603]
C6  DNP  [CAP0402]
C11  0.1uF  [cap0402]
C12  2.2uF  [CAP0402]
C13  10uF  [cap0603]
D12  GREEN  [led_0603]
FB1  180E  [FB0805]
FB6  180E  [FB0805]
R21  0R  [res0402]
R48  DNP  [res0603]
R53  DNP  [res0603]
R55  31.2K  [res0603]
R56  470R  [res0402]
R57  10K  [res0603]
R194  100K  [res0402]
VR1  MAX8869EUE50+T  [TSSOP_16P_EXP_0P65P_6P5X5P1MM]

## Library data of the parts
C16 C59 = C_0.01uF_50V_CER_0603
C44 C46 C58 C68 C74 C190 C257 C290 = C_10uf_CER_25V_0603: CAP CER 10UF 25V X5R 0603
C70 C151 C158 C162 C163 C203 C247 C254 C260 C269 C275 C293 = C_0.1uF_50V_CER_0402
C12 C72 C152 C206 C240 C268 = C_2.2uF_CER_25V_0402
D6 D12 D20 D32 D34 = LED_GREEN_0603
D15 D21-D26 D28 D29 D31 D33 D42-D51 = DIODE_SUPPRESSOR_ESD_30VDC_0402
D27 = LED_RED_CLEAR_0603_SMD-430MCD_2
1V8_LDO 2V5_LDO 3V3_D 3V3_LDO B4_1 B4_2 Done INIT = TP_SMD: Component Type: Test Point
FB5 FB12 FB13 FB18 FB19 FB28 FB33 = FB__220E_0603
J15 J18 = J_Header_14POS
Q1 = TRANS_NPN_45V_0.8A_SOT-23
R14 R93 R112 R133 R134 R136 = R_10K_0603
R30 = R_330R_0603
R58 R85 R108 R119 R123 R135 R229 R232 = R_4.7K_0603
R69 R114 = R_100R_0402
R105 R106 R118 = R_1K_0603
R107 R109 R111 R117 R120-R122 R223-R228 R230 R231 = R_0R_0603
SW3 = SWITCH_TACTILE_SPST-NO_0.05A_12
U11 = IC_MX25L51245GZ2I-08G_8-WDFN: IC FLASH 512MBIT SPI/QUAD 8WSON
R82 R83 = R_0.1R_0603
R110 = R_33R_0402
U9 = Y_OSC_50Mhz_0: MEMS OSC XO 125.0000MHZ CMOS SMD; Manufacturer Part No: ASEMB-125.000MHZ-XY-T; TEMP: -40°C ~ 105°C; TOLERANCE: ±10ppm
R32-R37 R39-R46 R50 R51 = R_100R_0201: RES 0 OHM JUMPER 1/20W 0201; Manufacturer: YAGEO; Manufacturer Part No: RC0201JR-070RL
R21 R47 R49 = R_0R_0402_0.063W
R216-R219 R221 R222 R237-R239 R243 R244 = R_4.7K_0402_5%_0.1W
R90 R124 R241 R242 = R_10K_0402_5%_0.1W_Au
FMC_VREF_A FMC_VREF_B = TP_SMD
J4 = ASP-134486-01: CONN ARRAY RCPT 400POS SMD GOLD; Component Type: FMC Connector; MSL: 1; Manufacturer: Samtec Inc.; ROHS/NON-ROHS: ROHS
R240 = R_1K_0402_1%_0.1W_Au
U8 = IC_JEDI_D1_672
C3 = CAP-0402: CAP CER 0.1UF 500V X7R 1210; Assy_OPT: P; Component Type: Ceremic Capacitor; MSL: 1; Manufacturer: KEMET; Manufacturer Part No: C1210C104KCRACTU; REUSE_ANNOTATE: TRUE; ROHS/NON-ROHS: ROHS; TEMP: -55°C ~ 125°C; TOLERANCE: ±10%; VOLTAGE RATED: 500V
C34 C69 = C_0.022uF_50V_CER_0603
C35 = C_4.7uF_10V_Cer_0402
C2 C11 C39 C54 C73 = C_0.1uF_25V_Cer-0402
C5 C13 C43 C45 C57 C78 = C_10uF_16V_Cer_0603
C49 C76 = C_1uF_50V_CER_0603
C60 C71 = C_330uF_10V_Tan_2917: MSL: 1
C65 = C_4.7uF_25V_CER_0603
C308 C312 = C_100uF_10V_Cer_1206
C309 C313 = C_47uF_1206_25V
FB1 FB6 FB20 FB26 FB30 = FB_180E_0805: ROHS/NON-ROHS: ROHS
J1-J3 J6 J20 J21 = CON1: Component Type: Mounting Hole
Q2 Q3 = TRANS_NPN_BC847C_SOT-23
R20 = R_1M_0805_1%_0.1W
R22 = R_2R_0805_1%_0.125W
R86 = R_2.87K_0402
R91 = R_3.57K_0402
R56 R94 R125 = R_470R_0402_1%_0.063W
R95 R127 = R_100R_0402_1%_0.063W_Au
R126 = R_1.2M_0603
R269 = R_453R_0603
U6 = VR_TPS74901RGWR_20-VQFN
U12 = VR_LMZ30604RKGT_39-B1QFN: DC DC CONVERTER 0.8-3.6V 14W
U13 = VR_BD00IC0WHFV-GTR_0
C6 = C_22nF_25V_CER_0402
R48 = R_10K_0603_0.1%_0.1W_Au: RES SMD 14.7KOHM 0.1% 1/10W 0603; Manufacturer: YAGEO; Manufacturer Part No: RT0603BRE0714K7L
R53 = R_10K_0603_0.1%_0.1W_Au: RES SMD 24.9KOHM 0.1% 1/10W 0603; Alternate PART NO: RT0603BRE0724K9L; Manufacturer: YAGEO; Manufacturer Part No: RT0603BRD0724K9L
R55 = R_31.2K_0603
R57 = R_10K_0603_0.1%_0.1W_Au
R194 = R_100K_0402_1%_0.063W: RES 100K OHM 1% 1/10W 0402; Manufacturer: Panasonic Electronic Components; Manufacturer Part No: ERJ-H2RF1003X
VR1 = VR_MAX8869EUE50+T_2: ROHS/NON-ROHS: ROHS

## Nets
1V8_LDO: C39.1 C45.1 FB18.2 ; also on sheet 15 17 18 20 21
1V8_OUT: R82.1 R83.1 ; also on sheet 14 16 21
3V3_AUX: FB5.2 J4.D32(3P3VAUX) R219.1 R221.1
3V3_OUT: C54.1 C57.1 C59.2 C76.1 FB5.1 FB20.1 FB26.2 J4.C39(3P3V1) J4.D36(3P3V2) J4.D38(3P3V4) J4.D40(3P3V3) J18.1 J18.2 R30.2 R94.1 R114.1 R125.1 R134.1 R216.2 R217.2 R237.1 R238.1 R239.1 R241.1 R242.1 R243.1 U9.1(STANDBY) U9.4(VCC) U13.6(VCC) ; also on sheet 13 14 16 17 18 21 22
5V: C35.1 FB1.1 FB30.1 R85.1 R93.2 R118.1 U6.10(BIAS) ; also on sheet 16 20 21
12V_IN: J4.C35(12P0V1) J4.C37(12P0V2) ; also on sheet 20
GND: C2.2 C5.2 C6.2 C11.2 C12.2 C13.2 C16.2 C34.1 C35.2 C39.2 C43.2 C44.2 C45.2 C46.2 C49.2 C54.2 C57.2 C58.2 C59.1 C60.2 C65.2 C68.2 C69.2 C70.2 C71.2 C72.2 C73.2 C74.2 C76.2 C78.2 C151.2 C152.2 C158.2 C162.2 C163.2 C190.2 C203.2 C206.2 C240.2 C247.2 C254.2 C257.2 C260.2 C268.2 C269.2 C275.2 C290.2 C293.2 C308.2 C309.2 C312.2 C313.2 D12.K D15.2(A2) D21.2(A2) D22.2(A2) D23.2(A2) D24.2(A2) D25.2(A2) D26.2(A2) D28.2(A2) D29.2(A2) D31.2(A2) D33.2(A2) D34.K D42.2(A2) D43.2(A2) D44.2(A2) D45.2(A2) D46.2(A2) D47.2(A2) D48.2(A2) D49.2(A2) D50.2(A2) D51.2(A2) J4.A1(GND1) J4.A4(GND2) J4.A5(GND3) J4.A8(GND4) J4.A9(GND5) J4.A12(GND6) J4.A13(GND7) J4.A16(GND8) J4.A17(GND9) J4.A20(GND10) J4.A21(GND11) J4.A24(GND12) J4.A25(GND13) J4.A28(GND14) J4.A29(GND15) J4.A32(GND16) J4.A33(GND17) J4.A36(GND18) J4.A37(GND19) J4.A40(GND20) J4.B2(GND21) J4.B3(GND22) J4.B6(GND23) J4.B7(GND24) J4.B10(GND25) J4.B11(GND26) J4.B14(GND27) J4.B15(GND28) J4.B18(GND29) J4.B19(GND30) J4.B22(GND31) J4.B23(GND32) J4.B26(GND33) J4.B27(GND34) J4.B30(GND35) J4.B31(GND36) J4.B34(GND37) J4.B35(GND38) J4.B38(GND39) J4.B39(GND40) J4.C1(GND41) J4.C4(GND42) J4.C5(GND43) J4.C8(GND44) J4.C9(GND45) J4.C12(GND46) J4.C13(GND47) J4.C16(GND48) J4.C17(GND49) J4.C20(GND50) J4.C21(GND51) J4.C24(GND52) J4.C25(GND53) J4.C28(GND54) J4.C29(GND55) J4.C32(GND56) J4.C33(GND57) J4.C36(GND58) J4.C38(GND59) J4.C40(GND60) J4.D2(GND61) J4.D3(GND62) J4.D6(GND63) J4.D7(GND64) J4.D10(GND65) J4.D13(GND66) J4.D16(GND67) J4.D19(GND68) J4.D22(GND69) J4.D25(GND70) J4.D28(GND71) J4.D37(GND72) J4.D39(GND73) J4.E1(GND74) J4.E4(GND75) J4.E5(GND76) J4.E8(GND77) J4.E11(GND78) J4.E14(GND79) J4.E17(GND80) J4.E20(GND81) J4.E23(GND82) J4.E26(GND83) J4.E29(GND84) J4.E32(GND85) J4.E35(GND86) J4.E38(GND87) J4.E40(GND88) J4.F2(GND89) J4.F3(GND90) J4.F6(GND91) J4.F9(GND92) J4.F12(GND93) J4.F15(GND94) J4.F18(GND95) J4.F21(GND96) J4.F24(GND97) J4.F27(GND98) J4.F30(GND99) J4.F33(GND100) J4.F36(GND101) J4.F39(GND102) J4.G1(GND103) J4.G4(GND104) J4.G5(GND105) J4.G8(GND106) J4.G11(GND107) J4.G14(GND108) J4.G17(GND109) J4.G20(GND110) J4.G23(GND111) J4.G26(GND112) J4.G29(GND113) J4.G32(GND114) J4.G35(GND115) J4.G38(GND116) J4.G40(GND117) J4.H3(GND118) J4.H6(GND119) J4.H9(GND120) J4.H12(GND121) J4.H14(LA07_N) J4.H15(GND122) J4.H18(GND123) J4.H21(GND124) J4.H24(GND125) J4.H27(GND126) J4.H30(GND127) J4.H33(GND128) J4.H36(GND129) J4.H39(GND130) J4.J1(GND131) J4.J4(GND132) J4.J5(GND133) J4.J8(GND134) J4.J11(GND135) J4.J14(GND136) J4.J17(GND137) J4.J20(GND138) J4.J23(GND139) J4.J26(GND140) J4.J29(GND141) J4.J32(GND142) J4.J35(GND143) J4.J38(GND144) J4.J40(GND145) J4.K2(GND146) J4.K3(GND147) J4.K6(GND148) J4.K9(GND149) J4.K12(GND150) J4.K15(GND151) J4.K18(GND152) J4.K21(GND153) J4.K24(GND154) J4.K27(GND155) J4.K30(GND156) J4.K33(GND157) J4.K36(GND158) J4.K39(GND159) J15.13 J15.14 J18.11 J18.12 Q1.2(E) Q2.2(E) Q3.2(E) R22.1 R48.2 R53.2 R57.2 R86.2 R90.2 R105.2 R124.2 R126.2 R135.2 R136.2 R218.2 R222.2 R240.2 R244.2 R269.2 SW3.1 U6.12(GND) U6.21(THERMPAD) U8.AE12(PB106B/PCLKC4_3) U9.2(GND) U11.4(GND) U11.9(EP) U12.1(AGND) U12.5(AGND_1) U12.7(STSEL) U12.29(AGND_2) U12.33(AGND_3) U12.34(AGND_4) U12.37(PGND) U13.3(GND) U13.7(EP) VR1.10(GND) VR1.17(EP) ; also on sheet 13 14 15 16 17 18 19 20 21 22
GND_EARTH: C3.2 J1.1 J2.1 J3.1 J6.1 J20.1 J21.1 R20.2 ; also on sheet 13 16
VCCIO0: C68.1 C70.1 C293.1 FB28.1 J15.10 R58.1 R106.1 R108.1 R112.2 R119.1 R123.1 R229.2 R232.1 U11.8(VCC) ; also on sheet 21
VCCIO3_1V8: FB13.1 R83.2
VCCIO4_1V8: FB12.1 R82.2
VCCIO6_3V3: FB19.1 ; also on sheet 21
VDD_2V5: C73.1 C78.1 FB33.2 ; also on sheet 17
CONN_FLASH_CS#: D21.1(A1) J15.2 R120.2
CONN_FLASH_DQ0: D26.1(A1) J15.5 R111.2
CONN_FLASH_DQ1: D28.1(A1) J15.7 R121.2
CONN_FLASH_DQ2: D31.1(A1) J15.11 R122.2
CONN_FLASH_DQ3: D29.1(A1) J15.9 R107.2
CONN_FLASH_MCLK: D33.1(A1) J15.12 R109.2
CONN_INITN: D25.1(A1) J15.6 R227.2
CONN_PROGRAMN: D22.1(A1) J15.1 R225.2
DONE: D23.1(A1) Done.1 J15.4 R14.2 R112.1 U8.G5(PT136B/DONE)
DP1_M2C_N: J4.A3(DP1_M2C_N) R44.1
DP1_M2C_P: J4.A2(DP1_M2C_P) R39.1
DP2_C2M_N: J4.A27(DP2_C2M_N) R51.1
DP2_C2M_P: J4.A26(DP2_C2M_P) R46.1
DP2_M2C_N: J4.A7(DP2_M2C_N) R42.1
DP2_M2C_P: J4.A6(DP2_M2C_P) R43.1
DP3_C2M_N: J4.A31(DP3_C2M_N) R40.1
DP3_C2M_P: J4.A30(DP3_C2M_P) R41.1
DP4_C2M_N: J4.A35(DP4_C2M_N) R50.1
DP4_C2M_P: J4.A34(DP4_C2M_P) R45.1
DP4_M2C_N: J4.A15(DP4_M2C_N) R37.1
DP4_M2C_P: J4.A14(DP4_M2C_P) R32.1
DP5_C2M_N: J4.A39(DP5_C2M_N) R33.1
DP5_C2M_P: J4.A38(DP5_C2M_P) R34.1
DP5_M2C_N: J4.A19(DP5_M2C_N) R35.1
DP5_M2C_P: J4.A18(DP5_M2C_P) R36.1
DPLL_1PPS_CLKOUT_N: J4.G31(LA29_N) U8.AD12(PB112B/PCLKC3_0/ADC_CN4)
DPLL_1PPS_CLKOUT_P: J4.G30(LA29_P) U8.AC12(PB112A/PCLKT3_0/ADC_CP4)
DPLL_CLKOUT_0TN: J4.G3(CLK1_M2C_N) U8.AE3(PB156B/LRC_GPLL0C_IN/VREF3_2)
DPLL_CLKOUT_0TP: J4.G2(CLK1_M2C_P) U8.AD3(PB156A/LRC_GPLL0T_IN)
DPLL_CLKOUT_1N: J4.C23(LA18_N_CC) U8.AC11(PB118B/PCLKC3_1/COMP2IN)
DPLL_CLKOUT_1P: J4.C22(LA18_P_CC) U8.AB11(PB118A/PCLKT3_1/COMP2IP)
DPLL_CLKOUT_2N: J4.B21(GBTCLK1_M2C_N) ; also on sheet 17
DPLL_CLKOUT_2P: J4.B20(GBTCLK1_M2C_P) ; also on sheet 17
DPLL_CLKOUT_10MHz_N: J4.H5(CLK0_M2C_N) U8.AC4(PB154B/PCLKC3_3/ADC_CN15)
DPLL_CLKOUT_10MHz_P: J4.H4(CLK0_M2C_P) U8.AB4(PB154A/PCLKT3_3/ADC_CP15)
DPLL_CSB: J4.C26(LA27_P) ; also on sheet 14
DPLL_FDEC: J4.D26(LA26_P) ; also on sheet 14
DPLL_FINC: J4.D27(LA26_N) ; also on sheet 14
DPLL_FLEXIO_1: J4.D21(LA17_N_CC) ; also on sheet 14
DPLL_FLEXIO_2: J4.D18(LA13_N) ; also on sheet 14
DPLL_I2C_SCL: D45.1(A1) J4.C30(SCL) J18.10 R217.1 ; also on sheet 14
DPLL_I2C_SDA: D43.1(A1) J4.C31(SDA) J18.14 R216.1 ; also on sheet 14
DPLL_I2C_SPI0: J4.C18(LA14_P) ; also on sheet 14
DPLL_INTRB: J4.D14(LA09_P) ; also on sheet 14
DPLL_OEB: J4.D15(LA09_N) ; also on sheet 14
DPLL_PLL_SEL0: J4.D23(LA23_P) ; also on sheet 14
DPLL_PLL_SEL1: J4.D24(LA23_N) ; also on sheet 14
DPLL_SDO: J4.C27(LA27_N) ; also on sheet 14
F_CLKIN_125Mhz: R110.2 U8.P24(PL42A/PCLKT6_0)
F_FLASH_CS#: R117.2 R119.2 R120.1 U11.1(CS#) ; also on sheet 19
F_FLASH_DQ0: R111.1 R226.2 U11.5(SI/SIO0) ; also on sheet 19
F_FLASH_DQ1: R121.1 R231.2 U11.2(SO/SIO1) ; also on sheet 19
F_FLASH_DQ2: R122.1 R123.2 R230.2 U11.3(WP#/SIO2) ; also on sheet 19
F_FLASH_DQ3: R107.1 R108.2 R224.2 U11.7(RESET#/SIO3) ; also on sheet 19
F_FLASH_MCLK: C58.1 R105.1 R106.2 R109.1 R223.2 U11.6(SCLK) ; also on sheet 19
F_PCIe_EC_PRSNT#: U8.R26(PL51B) ; also on sheet 17
F_SFP1_ABS: U8.P21(PL44B) ; also on sheet 18
F_SFP1_I2C_SCL: U8.P22(PL44A/PCLKT6_1) ; also on sheet 18
F_SFP1_I2C_SDA: U8.P23(PL42B) ; also on sheet 18
F_SFP1_LOS: U8.R20(PL46A/PCLKT6_2) ; also on sheet 18
F_SFP1_TX_DISABLE: U8.P25(PL40B) ; also on sheet 18
F_SFP1_TX_FAULT: U8.P26(PL40A) ; also on sheet 18
F_SFP2_ABS: U8.T22(PL49B) ; also on sheet 18
F_SFP2_I2C_SCL: U8.R22(PL49A) ; also on sheet 18
F_SFP2_I2C_SDA: U8.R18(PL47B) ; also on sheet 18
F_SFP2_LOS: U8.R25(PL51A) ; also on sheet 18
F_SFP2_TX_DISABLE: U8.R19(PL47A) ; also on sheet 18
F_SFP2_TX_FAULT: U8.R21(PL46B) ; also on sheet 18
F_SFP3_ABS: U8.U22(PL62A) ; also on sheet 13
F_SFP3_I2C_SCL: U8.U19(PL60A) ; also on sheet 13
F_SFP3_I2C_SDA: U8.T18(PL58B) ; also on sheet 13
F_SFP3_LOS: U8.U18(PL60B) ; also on sheet 13
F_SFP3_TX_DISABLE: U8.T19(PL58A) ; also on sheet 13
F_SFP3_TX_FAULT: U8.T20(PL56B) ; also on sheet 13
F_SFP4_ABS: U8.V21(PL67B) ; also on sheet 13
F_SFP4_I2C_SCL: U8.V19(PL65B) ; also on sheet 13
F_SFP4_I2C_SDA: U8.V18(PL65A) ; also on sheet 13
F_SFP4_LOS: U8.V20(PL67A) ; also on sheet 13
F_SFP4_TX_DISABLE: U8.U25(PL64B) ; also on sheet 13
F_SFP4_TX_FAULT: U8.U24(PL64A) ; also on sheet 13
FMC_CLK2_M2C_N: J4.K5(CLK2_M2C_N) U8.AB18(PB58B/PCLKC4_1)
FMC_CLK2_M2C_P: J4.K4(CLK2_M2C_P) U8.AB19(PB58A/PCLKT4_1)
FMC_CLK3_M2C_N: J4.J3(CLK3_M2C_N) U8.AB13(PB100B/PCLKC4_2/ADC_CN7)
FMC_CLK3_M2C_P: J4.J2(CLK3_M2C_P) U8.AA13(PB100A/PCLKT4_2/ADC_CP7)
FMC_GA0: J4.C34(GA0) R221.2 R222.1
FMC_GA1: J4.D35(GA1) R218.1 R219.2
FMC_HA02_N: J4.K8(HA02_N) U8.AC19(PB56B)
FMC_HA02_P: J4.K7(HA02_P) U8.AD20(PB56A)
FMC_HA03_N: J4.J7(HA03_N) U8.AA18(PB60B)
FMC_HA03_P: J4.J6(HA03_P) U8.Y18(PB60A)
FMC_HA04_N: J4.F8(HA04_N) U8.AF11(PB114B/COMP1IN)
FMC_HA04_P: J4.F7(HA04_P) U8.AF12(PB114A/COMP1IP)
FMC_HA05_N: J4.E7(HA05_N) U8.AE11(PB116B/ADC_CN8)
FMC_HA05_P: J4.E6(HA05_P) U8.AD11(PB116A/ADC_CP8)
FMC_HA06_N: J4.K11(HA06_N) U8.Y17(PB82B)
FMC_HA06_P: J4.K10(HA06_P) U8.AA17(PB82A)
FMC_HA07_N: J4.J10(HA07_N) U8.W16(PB84B)
FMC_HA07_P: J4.J9(HA07_P) U8.Y16(PB84A)
FMC_HA08_N: J4.F11(HA08_N) U8.AA11(PB120B/ADC_CN13)
FMC_HA08_P: J4.F10(HA08_P) U8.Y11(PB120A/ADC_CP13)
FMC_HA09_N: J4.E10(HA09_N) U8.W10(PB122B)
FMC_HA09_P: J4.E9(HA09_P) U8.W11(PB122A)
FMC_HA10_N: J4.K14(HA10_N) U8.AC15(PB86B)
FMC_HA10_P: J4.K13(HA10_P) U8.AB15(PB86A)
FMC_HA11_N: J4.J13(HA11_N) U8.AE15(PB88B)
FMC_HA11_P: J4.J12(HA11_P) U8.AD15(PB88A)
FMC_HA12_N: J4.F14(HA12_N) U8.AA10(PB124B)
FMC_HA12_P: J4.F13(HA12_P) U8.Y10(PB124A)
FMC_HA13_N: J4.E13(HA13_N) U8.AF9(PB126B)
FMC_HA13_P: J4.E12(HA13_P) U8.AF10(PB126A)
FMC_HA14_N: J4.J16(HA14_N) U8.AF16(PB90B)
FMC_HA14_P: J4.J15(HA14_P) U8.AF15(PB90A)
FMC_HA15_N: J4.F17(HA15_N) U8.AE10(PB128B)
FMC_HA15_P: J4.F16(HA15_P) U8.AD10(PB128A)
FMC_HA16_N: J4.E16(HA16_N) U8.AE9(PB130B)
FMC_HA16_P: J4.E15(HA16_P) U8.AD9(PB130A)
FMC_HA17_N_CC: J4.K17(HA17_N_CC) ; also on sheet 13
FMC_HA17_P_CC: J4.K16(HA17_P_CC) ; also on sheet 13
FMC_HA18_N: J4.J19(HA18_N) U8.W14(PB92B)
FMC_HA18_P: J4.J18(HA18_P) U8.W15(PB92A)
FMC_HA19_N: J4.F20(HA19_N) U8.AC9(PB132B)
FMC_HA19_P: J4.F19(HA19_P) U8.AB9(PB132A)
FMC_HA20_N: J4.E19(HA20_N) U8.AB7(PB134B)
FMC_HA20_P: J4.E18(HA20_P) U8.AC7(PB134A)
FMC_HA21_N: J4.K20(HA21_N) U8.AA14(PB94B)
FMC_HA21_P: J4.K19(HA21_P) U8.Y14(PB94A)
FMC_HA22_N: J4.J22(HA22_N) U8.AE14(PB96B)
FMC_HA22_P: J4.J21(HA22_P) U8.AD14(PB96A)
FMC_HA23_N: J4.K23(HA23_N) U8.Y13(PB98B/ADC_CN5)
FMC_HA23_P: J4.K22(HA23_P) U8.W13(PB98A/ADC_CP5)
FMC_LA19_N: J4.H23(LA19_N) U8.AF5(PB138B)
FMC_LA19_P: J4.H22(LA19_P) U8.AF6(PB138A)
FMC_LA21_N: J4.H26(LA21_N) U8.AE6(PB140B)
FMC_LA21_P: J4.H25(LA21_P) U8.AD6(PB140A)
FMC_LA24_N: J4.H29(LA24_N) U8.AC6(PB142B)
FMC_LA24_P: J4.H28(LA24_P) U8.AB6(PB142A)
FMC_LA28_N: J4.H32(LA28_N) U8.AE5(PB144B)
FMC_LA28_P: J4.H31(LA28_P) U8.AD5(PB144A)
FMC_LA30_N: J4.H35(LA30_N) U8.AA6(PB146B/ADC_CN14)
FMC_LA30_P: J4.H34(LA30_P) U8.Y6(PB146A/ADC_CP14)
FMC_LA32_N: J4.H38(LA32_N) U8.AF3(PB150B/ADC_CN11)
FMC_LA32_P: J4.H37(LA32_P) U8.AF4(PB150A/ADC_CP11)
FMC_OCXO_EN: J4.G28(LA25_N) ; also on sheet 14
FMC_PG_FPGA: D51.1(A1) J4.F1(PG_M2C) J18.4 R242.2 ; also on sheet 19
FMC_PRST_M2C_L: D47.1(A1) J4.H2(PRSNT_M2C_L) J18.8 R243.2 R244.1 ; also on sheet 19
FMC_RES_0: R49.2
FMC_RES_1: R47.2
FMC_TCK: D50.1(A1) J4.D29(TCK) J18.3 R240.1 ; also on sheet 19
FMC_TDI: D46.1(A1) J4.D30(TDI) J18.7 R239.2 ; also on sheet 19
FMC_TDO: D44.1(A1) J4.D31(TDO) J18.9 R238.2 ; also on sheet 19
FMC_TMS: D42.1(A1) J4.D33(TMS) J18.13 R237.2 ; also on sheet 19
FMC_ToD_CLK_FPGA_N: J4.D9(LA01_N_CC) U8.AA5(PB148B/PCLKC3_2/COMP3IN)
FMC_ToD_CLK_FPGA_P: J4.D8(LA01_P_CC) U8.Y5(PB148A/PCLKT3_2/COMP3IP)
FMC_ToD_IN: J4.D11(LA05_P) ; also on sheet 19
FMC_ToD_OUT: J4.D12(LA05_N) ; also on sheet 19
FMC_TRST_L: D49.1(A1) J4.D34(TRST_L) J18.6
FMC_VADJ_3V3: C12.1 FB6.2 J4.E39(VADJ1) J4.F40(VADJ2) J4.G39(VADJ3) J4.H40(VADJ4)
FPGA_CLKOUT_10MHz_N: J4.C11(LA06_N) ; also on sheet 13
FPGA_CLKOUT_10MHz_P: J4.C10(LA06_P) ; also on sheet 13
FPGA_DPLL_RESET_N: J4.C19(LA14_N) ; also on sheet 14
FPGA_FMC_GPIO_1: J4.G6(LA00_P_CC) U8.AE13(PB106A/PCLKT4_3)
FPGA_FMC_GPIO_4: J4.G15(LA12_P) U8.AE19(PB64B)
FPGA_FMC_GPIO_5: J4.G18(LA16_P) U8.AF21(PB66A)
FPGA_FMC_GPIO_6: J4.G21(LA20_P) U8.AF20(PB66B)
FPGA_FMC_GPIO_7: J4.G24(LA22_P) U8.AC18(PB80A)
FPGA_FMC_GPIO_8: J4.G27(LA25_P) U8.AD18(PB80B)
FPGA_FMC_GPIO_SYNC_N: J4.G13(LA08_N) U8.AF23(PB54B)
FPGA_FMC_GPIO_SYNC_P: J4.G12(LA08_P) U8.AF22(PB54A)
FPGA_FMC_GPIO_SYS_REF_N: J4.G10(LA03_N) U8.W18(PB62B)
FPGA_FMC_GPIO_SYS_REF_P: J4.G9(LA03_P) U8.W17(PB62A)
FPGA_GNSS_RESET_N: J4.H16(LA11_P) ; also on sheet 19
FPGA_PG_FMC: D48.1(A1) J4.D1(PG_C2M) J18.5 R241.2 ; also on sheet 19
FPGA_PPS_IN: J4.D17(LA13_P) ; also on sheet 19
FPGA_PPS_OUT: J4.D20(LA17_P_CC) ; also on sheet 19
GNSS_EXTINT0: J4.H19(LA15_P) ; also on sheet 19
GNSS_EXTINT1: J4.H20(LA15_N) ; also on sheet 19
GNSS_I2C_SCL: J4.H11(LA04_N) ; also on sheet 19
GNSS_I2C_SDA: J4.H10(LA04_P) ; also on sheet 19
GNSS_RX: J4.H8(LA02_N) ; also on sheet 19
GNSS_TIME_PULSE_2: J4.H13(LA07_P) ; also on sheet 19
GNSS_TX: J4.H7(LA02_P) ; also on sheet 19
INITN: D27.K INIT.1 R228.2
LLAb: J4.G33(LA31_P) ; also on sheet 14
LLBb: J4.G34(LA31_N) ; also on sheet 14
LLCb: J4.G36(LA33_P) ; also on sheet 14
LLDb: J4.G37(LA33_N) ; also on sheet 14
MCSNO: D24.1(A1) J15.3 U8.H3(PT142B/MCSNO/MSDO)
PROGRAMN: C16.1 R69.2 R225.1 R232.2 U8.G4(PT134B/PROGRAMN) ; also on sheet 16 19
PWRGD_3V3: D34.A R118.2 U12.27(PWRGD)
SD4_RX_N_FMC_TX_N: R37.2 R44.2 ; also on sheet 17
SD4_RX_P_FMC_TX_P: R32.2 R39.2 ; also on sheet 17
SD4_TX_N_FMC_RX_N: R50.2 R51.2 ; also on sheet 17
SD4_TX_P_FMC_RX_P: R45.2 R46.2 ; also on sheet 17
SD5_RX_N_FMC_TX_N: R35.2 R42.2 ; also on sheet 17
SD5_RX_P_FMC_TX_P: R36.2 R43.2 ; also on sheet 17
SD5_TX_N_FMC_RX_N: R33.2 R40.2 ; also on sheet 17
SD5_TX_P_FMC_RX_P: R34.2 R41.2 ; also on sheet 17
SyncE_RX_Clk_FMC_N: J4.C15(LA10_N) ; also on sheet 13
SyncE_RX_Clk_FMC_P: J4.C14(LA10_P) ; also on sheet 13
SyncE_TX_CLK_FPGA_N: J4.D5(GBTCLK0_M2C_N) ; also on sheet 17
SyncE_TX_CLK_FPGA_P: J4.D4(GBTCLK0_M2C_P) ; also on sheet 17
N13993571: C268.1 C275.1 C290.1 FB28.2 U8.H5(VCCIO0)
N14168065: D15.1(A1) R58.2 R69.1 SW3.2
N14168483: R227.1 R228.1 R229.1 U8.G2(PT134A/INITN)
N14179828: D27.A R114.2
N17779654: C71.1 C308.1 C309.1 FB30.2 U12.30(VIN) U12.31(VIN_1) U12.32(VIN_2)
N17779765: 3V3_D.1 C60.1 C65.1 C312.1 C313.1 FB26.1 U12.8(VOUT) U12.9(VOUT_1) U12.10(VOUT_2) U12.11(VOUT_3) U12.12(VOUT_4) U12.13(VOUT_5) U12.14(VOUT_6) U12.36(SENSE+) U12.38(VOUT_7)
N17779857: R269.1 U12.35(VADJ)
N17779873: C69.1 U12.6(SS/TR)
N17779891: R126.1 U12.4(RT/CLK)
N17779937: U12.17(PH) U12.18(PH_1) U12.19(PH_2) U12.20(PH_3) U12.21(PH_4) U12.22(PH_5) U12.23(PH_6) U12.24(PH_7) U12.25(PH_8) U12.39(PH_9)
N18151031: D6.A R30.1
N18151076: Q1.1(B) R14.1
N18634044: R223.1 U8.G6(PT136A/MCLK/PCLKT0_0)
N18634175: R117.1 U8.G7(PT138A/MCSN/PCLKT0_1)
N18634324: R226.1 U8.H7(PT138B/MOSI/MD0)
N18634341: R231.1 U8.H6(PT140A/MISO/MD1/OSC_HI)
N18634358: R230.1 U8.K5(PT140B/MD2)
N18634375: R224.1 U8.H4(PT142A/MD3)
N18757991: C240.1 C247.1 C254.1 C257.1 C260.1 C269.1 FB13.2 U8.AB5(VCCIO3) U8.AB8(VCCIO3) U8.AB10(VCCIO3)
N18757997: C162.1 C163.1 C190.1 C203.1 C206.1 FB12.2 U8.AB14(VCCIO4) U8.AB17(VCCIO4) U8.AD19(VCCIO4)
N18813734: C43.1 C49.1 FB20.2 U6.5(IN1) U6.6(IN2) U6.7(IN3) U6.8(IN4)
N18813742: R93.1 U6.9(PG)
N18813768: 1V8_LDO.1 C46.1 FB18.1 R91.1 R95.2 U6.1(OUT1) U6.18(OUT2) U6.19(OUT3) U6.20(OUT4)
N18813826: R86.1 R91.2 U6.16(FB)
N18813838: R85.2 U6.11(EN)
N18853491: D6.K Q1.3(C)
N19459286: 2V5_LDO.1 C72.1 C74.1 FB33.1 R127.1 R133.1 U13.1(Vout)
N19459395: R133.2 R135.1 U13.2(FB)
N19459407: R134.2 R136.1 U13.4(EN)
N19535953: C44.1 C151.1 C152.1 C158.1 FB19.2 U8.R23(VCCIO6) U8.U20(VCCIO6)
N19536529: R110.1 U9.3(OUT)
N19691926: J4.B1(RES1) R47.1
N19691949: J4.B40(RES0) R49.1
N19699743: FMC_VREF_A.1 J4.H1(VREF_A_M2C)
N19699763: FMC_VREF_B.1 J4.K1(VREF_B_M2C2)
N19710005: C2.1 C5.1 FB1.2 R21.2 VR1.2(IN) VR1.3(IN) VR1.4(IN) VR1.5(IN)
N19710534: 3V3_LDO.1 C11.1 C13.1 FB6.1 R55.1 R56.1 R194.1 VR1.12(OUT) VR1.13(OUT) VR1.14(OUT) VR1.15(OUT)
N19710650: R194.2 VR1.6(RST#)
N19711497: R48.1 R53.1 R55.2 R57.1 VR1.11(SET)
N19718593: C6.1 VR1.8(SS)
N19718685: R21.1 VR1.7(SHDN#)
N19765134: C3.1 R20.1 R22.2
N19810451: Q3.1(B) R124.1 R127.2
N19811941: D32.A R125.2
N19814299: D20.A R94.2
N19814326: Q2.1(B) R90.1 R95.1
N19926480: B4_1.1 U8.AD21(PB52A/PCLKT4_0)
N19926528: B4_2.1 U8.AE21(PB52B/PCLKC4_0)
N20212108: D32.K Q3.3(C)
N20212109: D20.K Q2.3(C)
N20212110: C34.2 U6.15(SS)
N20255499: D12.A R56.2

Not connected (* = marked no-connect by the designer): J4 A10(DP3_M2C_P) A11(DP3_M2C_N) A22(DP1_C2M_P) A23(DP1_C2M_N) B4(DP9_M2C_P) B5(DP9_M2C_N) B8(DP8_M2C_P) B9(DP8_M2C_N) B12(DP7_M2C_P) B13(DP7_M2C_N) B16(DP6_M2C_P) B17(DP6_M2C_N) B24(DP9_C2M_P) B25(DP9_C2M_N) B28(DP8_C2M_P) B29(DP8_C2M_N) B32(DP7_C2M_P) B33(DP7_C2M_N) B36(DP6_C2M_P) B37(DP6_C2M_N) C2(DP0_C2M_P) C3(DP0_C2M_N) C6(DP0_M2C_P) C7(DP0_M2C_N) E2(HA01_P_CC) E3(HA01_N_CC) E21(HB03_P) E22(HB03_N) E24(HB05_P) E25(HB05_N) E27(HB09_P) E28(HB09_N) E30(HB13_P) E31(HB13_N) E33(HB19_P) E34(HB19_N) E36(HB21_P) E37(HB21_N) F4(HA00_P_CC) F5(HA00_N_CC) F22(HB02_P) F23(HB02_N) F25(HB04_P) F26(HB04_N) F28(HB08_P) F29(HB08_N) F31(HB12_P) F32(HB12_N) F34(HB16_P) F35(HB16_N) F37(HB20_P) F38(HB20_N) G7(LA00_N_CC) G16(LA12_N) G19(LA16_N) G22(LA20_N) G25(LA22_N) H17(LA11_N) J24(HB01_P) J25(HB01_N) J27(HB07_P) J28(HB07_N) J30(HB11_P) J31(HB11_N) J33(HB15_P) J34(HB15_N) J36(HB18_P) J37(HB18_N) J39(VIO_B_M2C1) K25(HB00_P_CC) K26(HB00_N_CC) K28(HB06_P_CC) K29(HB06_N_CC) K31(HB10_P) K32(HB10_N) K34(HB14_P) K35(HB14_N) K37(HB17_P_CC) K38(HB17_N_CC) K40(VIO_B_M2C3); J15 8*; U6 2(NC1)* 3(NC2)* 4(NC3)* 13(NC4)* 14(NC5)* 17(NC6)*; U8 AA7(PB136A) AA12(PB110A/VREF3_1/ADC_CP10) AB12(PB110B/ADC_CN10) AC13(PB104A/ADC_CP9)* AD4(PB152A/ADC_CP12) AD13(PB104B/ADC_CN9)* AE4(PB152B/ADC_CN12) AE22(PB50A/VREF4_1) AE23(PB50B) AF13(PB102B/ADC_CN6)* AF14(PB102A/ADC_CP6)* AF19(PB64A)* H1(PT144B)* H2(PT144A)* J1(PT146A)* J2(PT146B)* J3(PT148A)* J5(PT148B)* J6(PT150A)* J7(PT150B)* K2(PT156B)* K3(PT156A)* K4(PT154B)* K6(PT154A)* K7(PT152B)* K8(PT152A)* T21(PL56A)* T23(PL55B)* T24(PL55A)* T25(PL53B)* T26(PL53A)* U23(PL62B)* W12(PB108B/VREF4_2)* Y7(PB136B) Y12(PB108A)*; U12 2(DNC)* 3(DNC_1)* 15(DNC_2)* 16(DNC_3)* 26(DNC_4)* 28(INH/UVLO)*; U13 5(NC)*; VR1 1(NC)* 9(NC)* 16(NC)*

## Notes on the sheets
sheet 1
- 5V to 3.3V
- Place 24.9K to Provide 1.8V(R53)
- Place 14.7K to Provide 2.5V(R48)
sheet 2
- FMC_Conf_Header
sheet 3
- Clock_Tree
sheet 4
- PWR Tree
sheet 5
- Revision_record
- Revision
- Date
- Description of change
- Author
- v1.0
- June 21, 2022
- First Release
- Added control signals for DPLL status
  Renamed DPLL output signals
  (FMC_ToD & OUT7_P/N)
  Moved 1G SFP Port0 RX signal to CDR pins
- v2.0
- Jan 24, 2023
- Renamed DPLL Output and Input signals as per
  application
  Added PROGRAMN pin to FPGA GPIO on Bank7
  Added DPLL Loss of Lock and FLEXIO signals to
  FPGA
- v2.1
- Jul 25, 2023
sheet 6
- Primary Reference Clock
- BANK 6
  3.3V
sheet 8
- 5V-3.3V FOR FPGA,LDOs
- 3.3V-1.8V
  FOR FPGA
- 3.3V to 2.5V
  FOR Oscillator
sheet 9
- BANK 4
- BANK 3
- 1.8V
- 1.8V
sheet 10
- INDEX
- 01_Index
  02_Title_Block
  03_Block-Diagram
  04_Clock_Tree
  05_PWR_Tree
  06_FPGA_SerDes-PCIe
  07_SerDes_PWR,2-10G SFPs
  08_FPGA_B0-Config
  09_FPGA_B1-Led,7Seg,FTDI_Ctrl
  10_FPGA_B2-WR_Header
  11_FPGA_B3_B4-FMC
  12_FPGA_B5-2-1G_SFPS
  13_FPGA_B6-SFPS_Ctrl
  14_FPGA_B7-
  15_FPGA_ADC
  16_FTDI_USB
  17_FMC_Connector
  18_FMC_Connector
  19_PS-5V,1V
  20_PS-1V8,1VLDO
  21_PS-3V3,1V8LDO,2V5LDO
  22_PS-FMC_3V3_LDO
sheet 11
- BLOCK DIAGRAM
sheet 12
- PROGRAMN
- BANK 0
  3.3V
- INITN LED
- SPI Boot FLASH
- DONE LED
- 1 st preference to
  connect the spi llines to
  FPGA Bank 0
- 512Mbit seiral
  NoR 3.3V rated
- Parallel / SPI Config Header
